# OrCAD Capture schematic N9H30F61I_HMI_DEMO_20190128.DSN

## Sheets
1 Main Block: size B; title: N9H30F51I_HMI_DEMO; rev: 1.0; note: MAIN_BLOCK
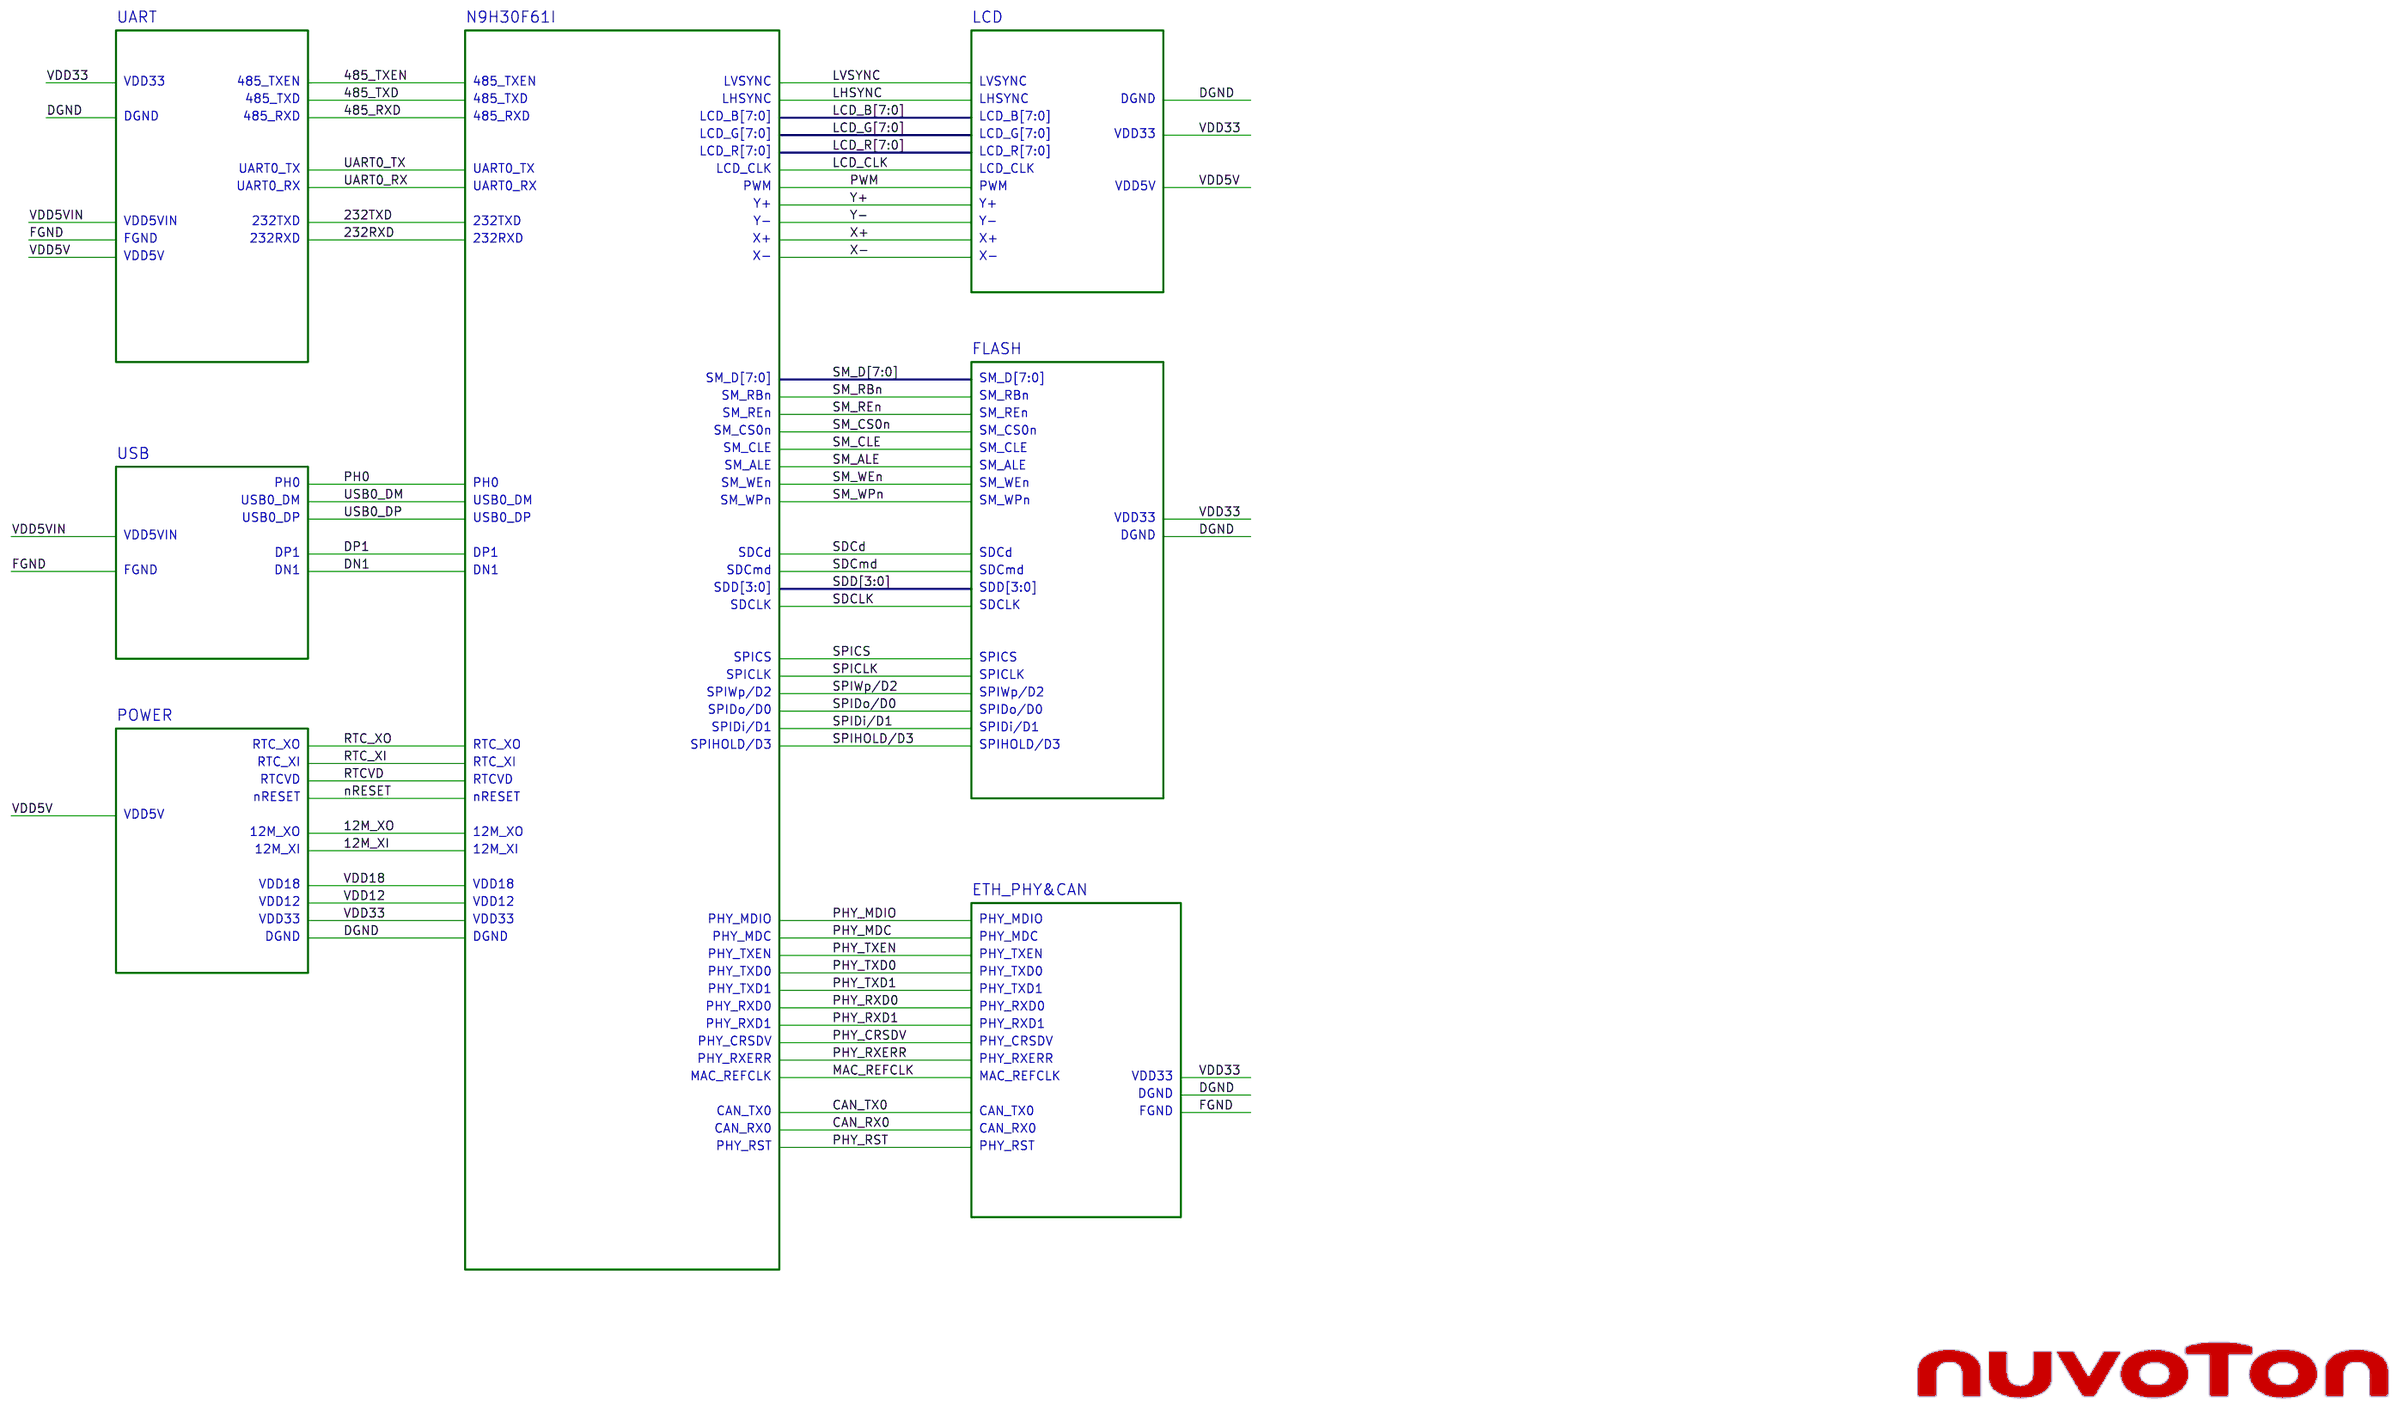
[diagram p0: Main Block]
2 N9H30F61I: size Custom; note: N9H30F51I; block N9H30F61I
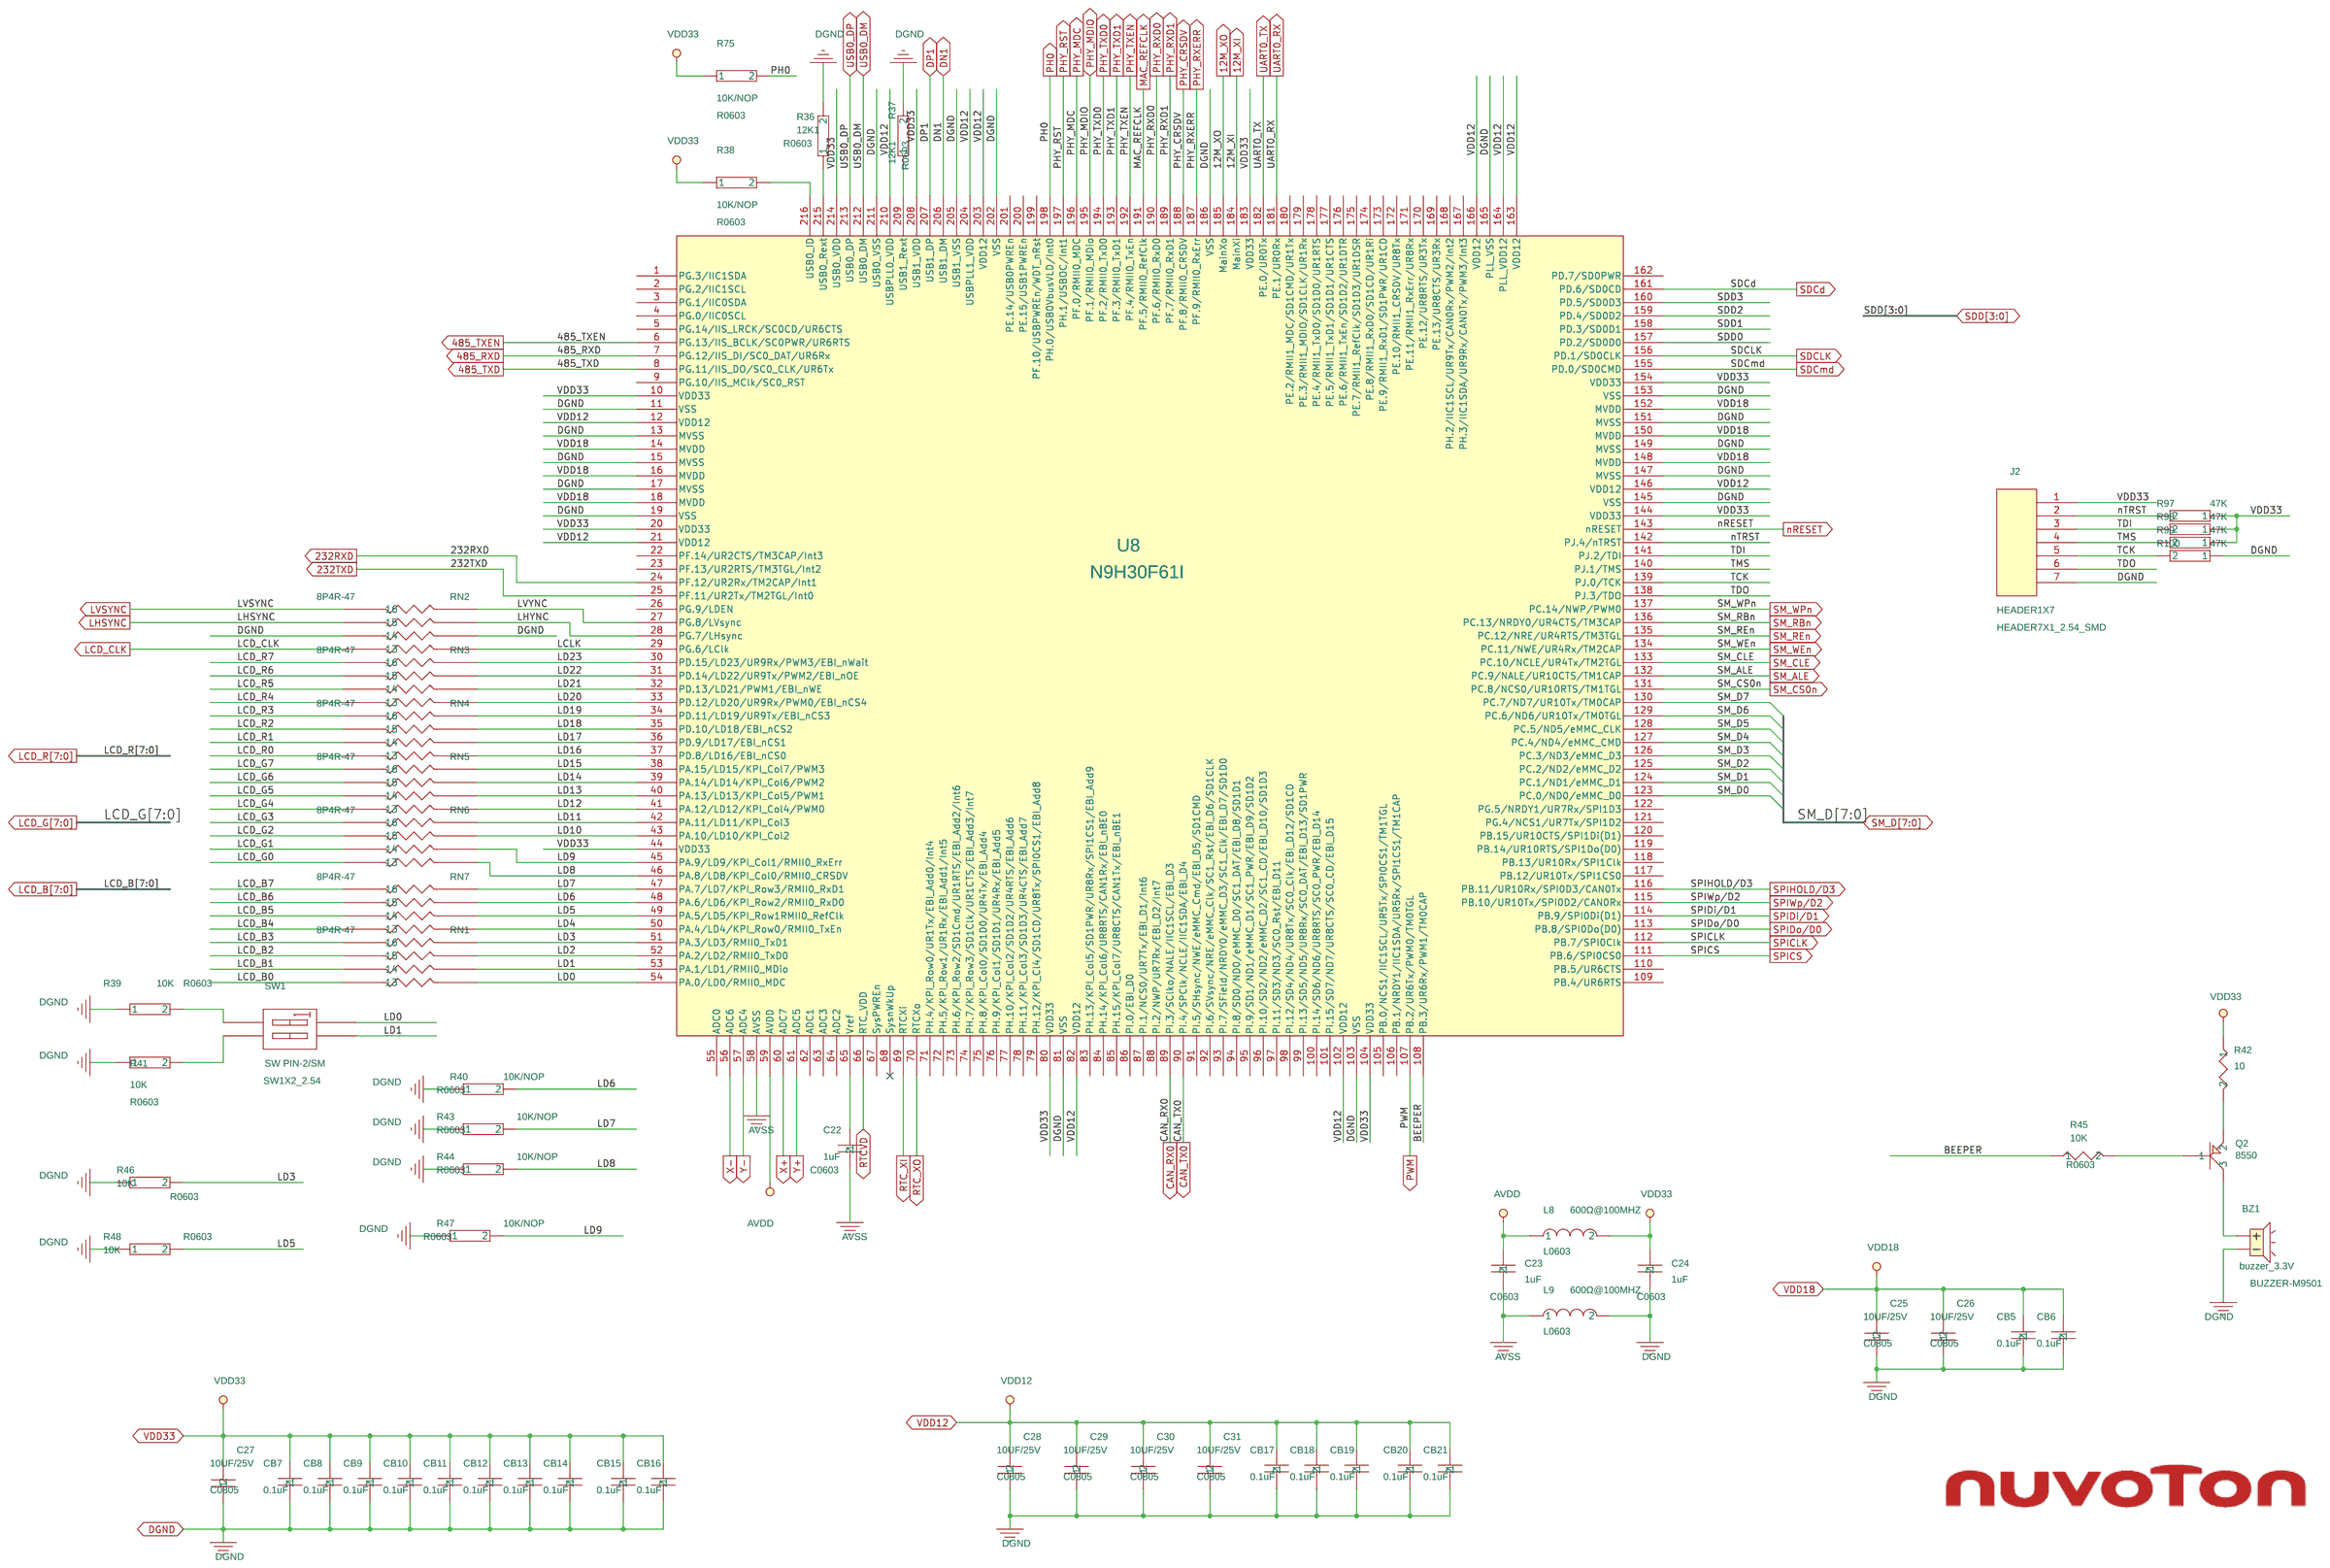
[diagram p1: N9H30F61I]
3 LCD: size B; note: LCD; block LCD
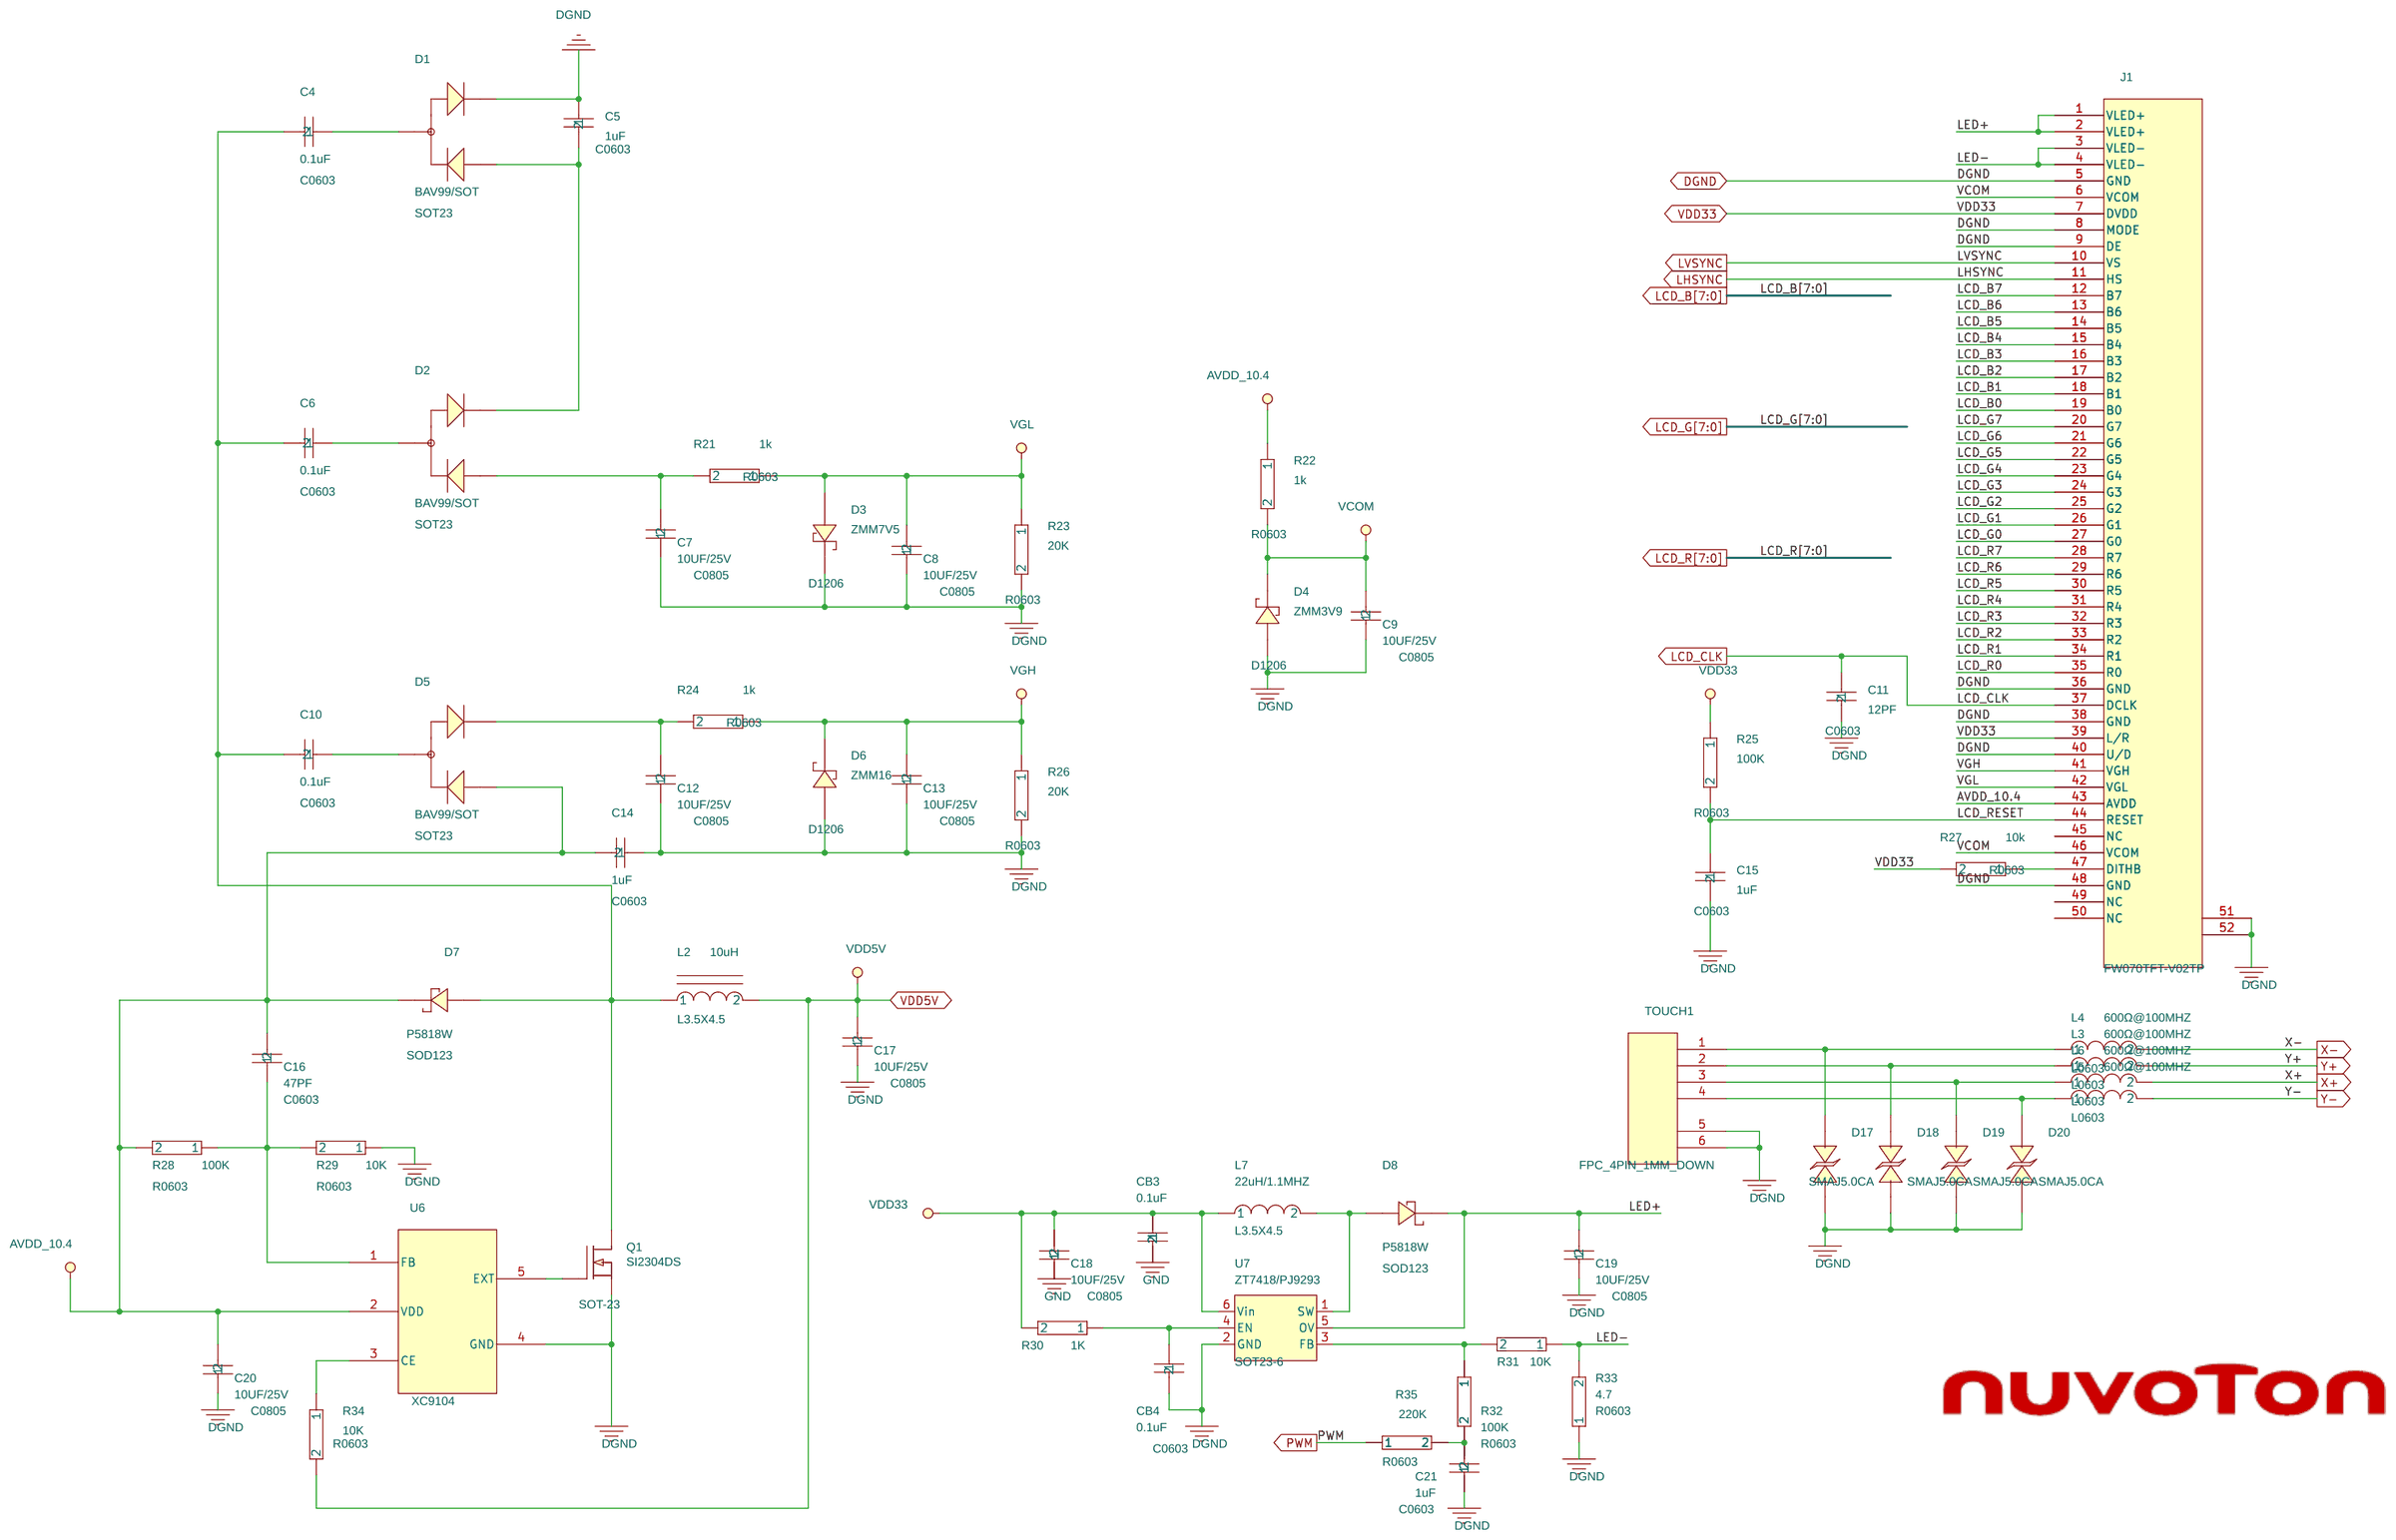
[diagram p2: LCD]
4 Flash: size A; note: Flash; block FLASH
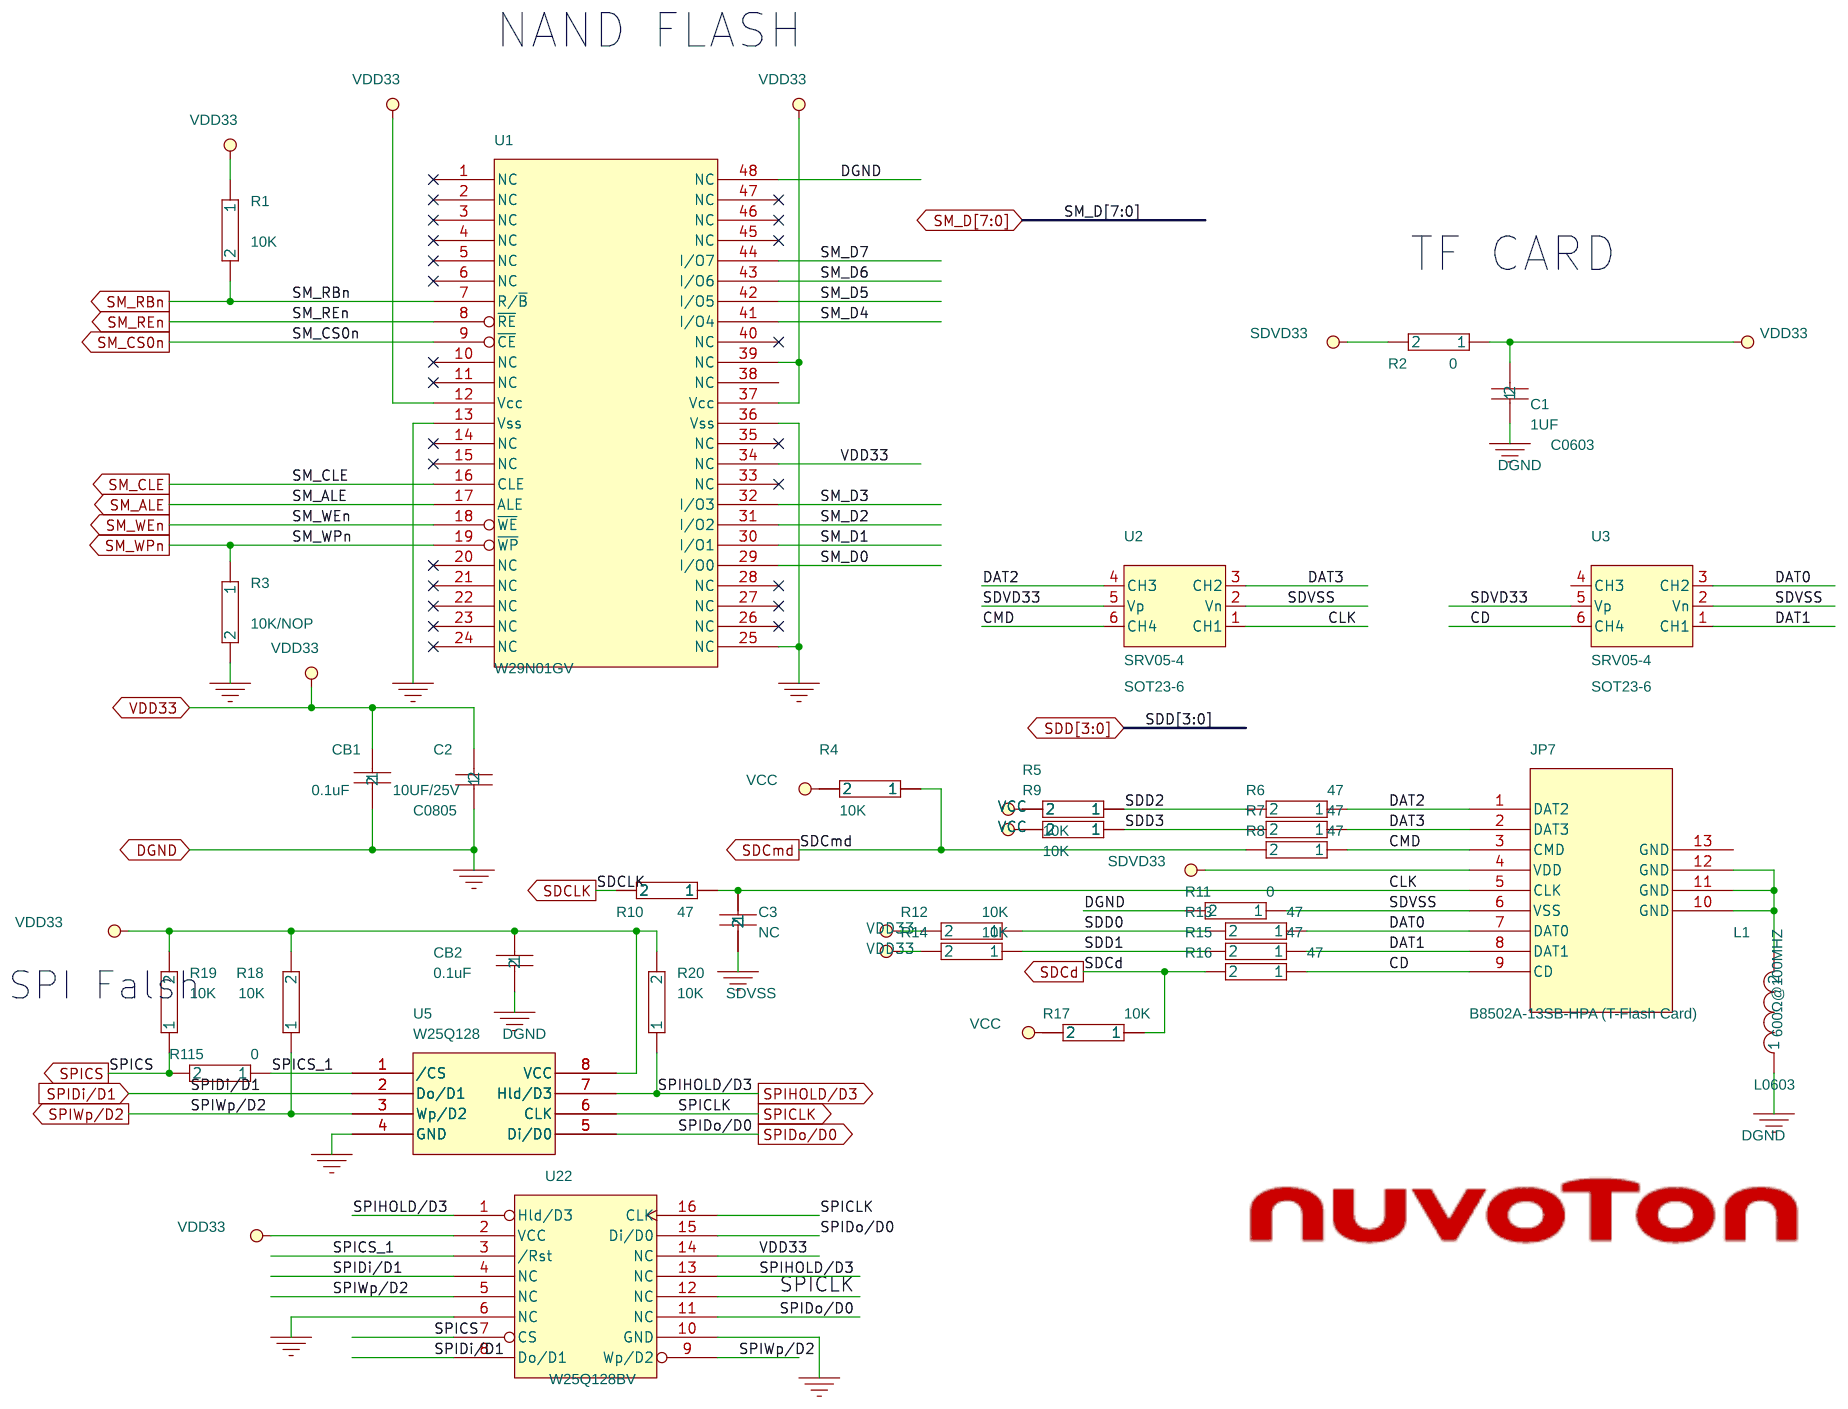
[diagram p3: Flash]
5 ETH_PHY&CAN: size B; note: ETH_PHY&CAN; block ETH_PHY&CAN
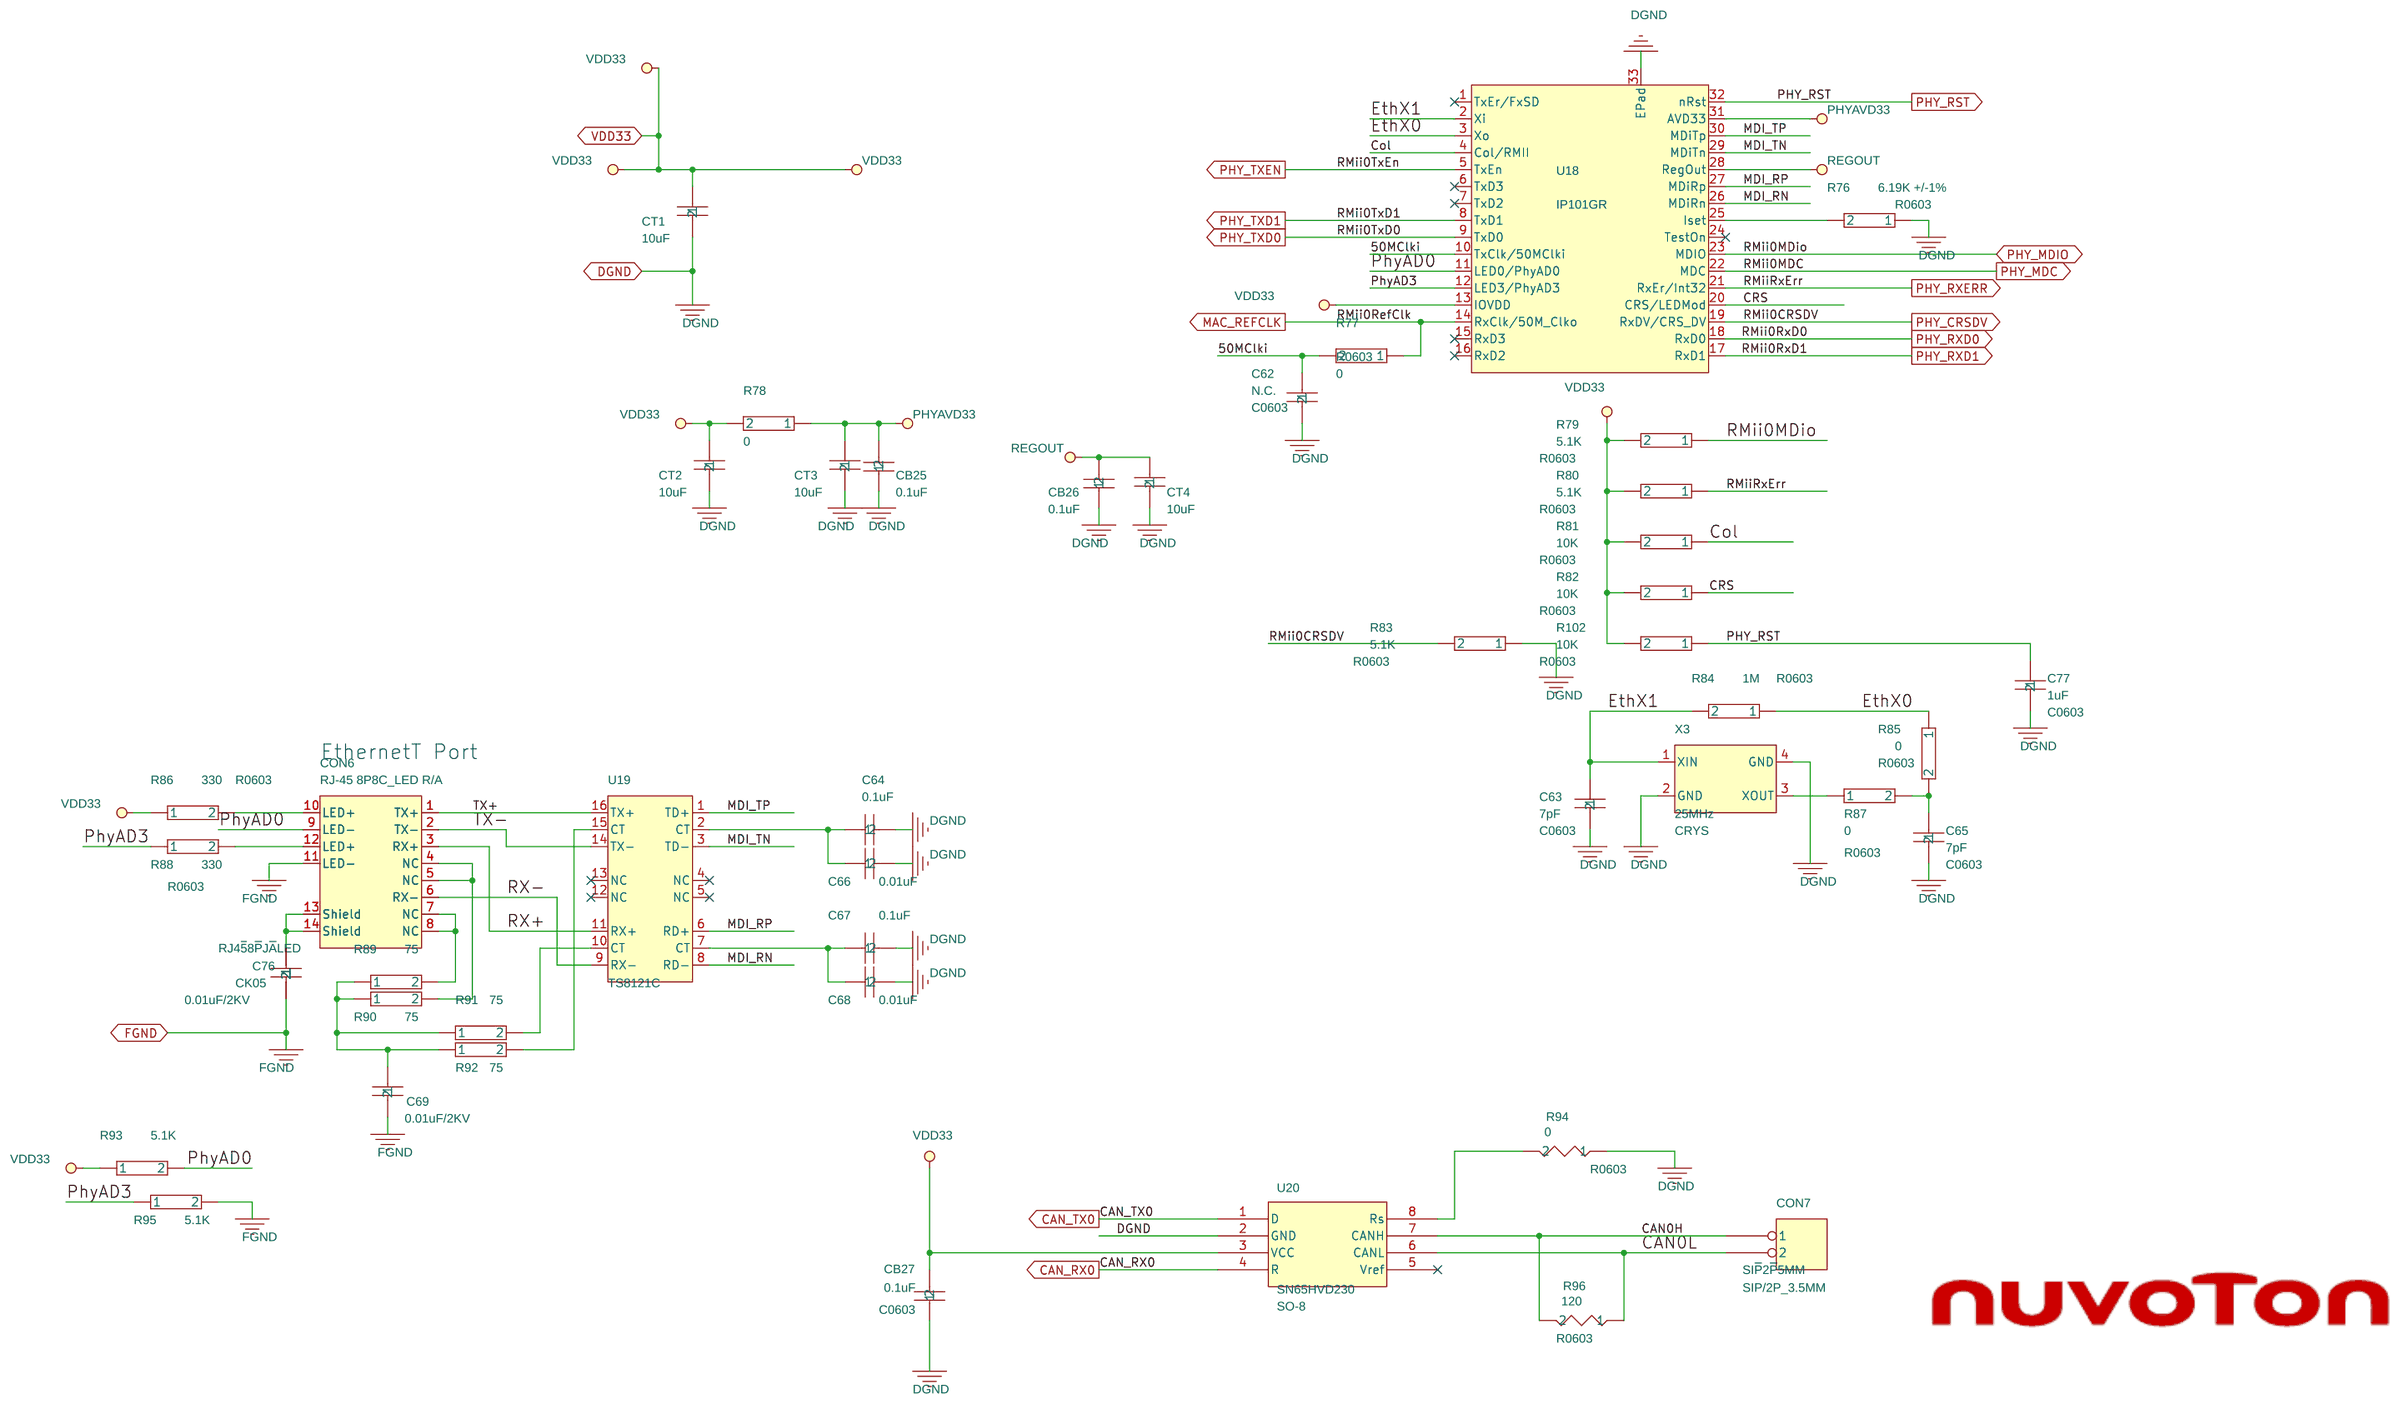
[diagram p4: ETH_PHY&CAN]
6 UART: size B; note: UART; block UART
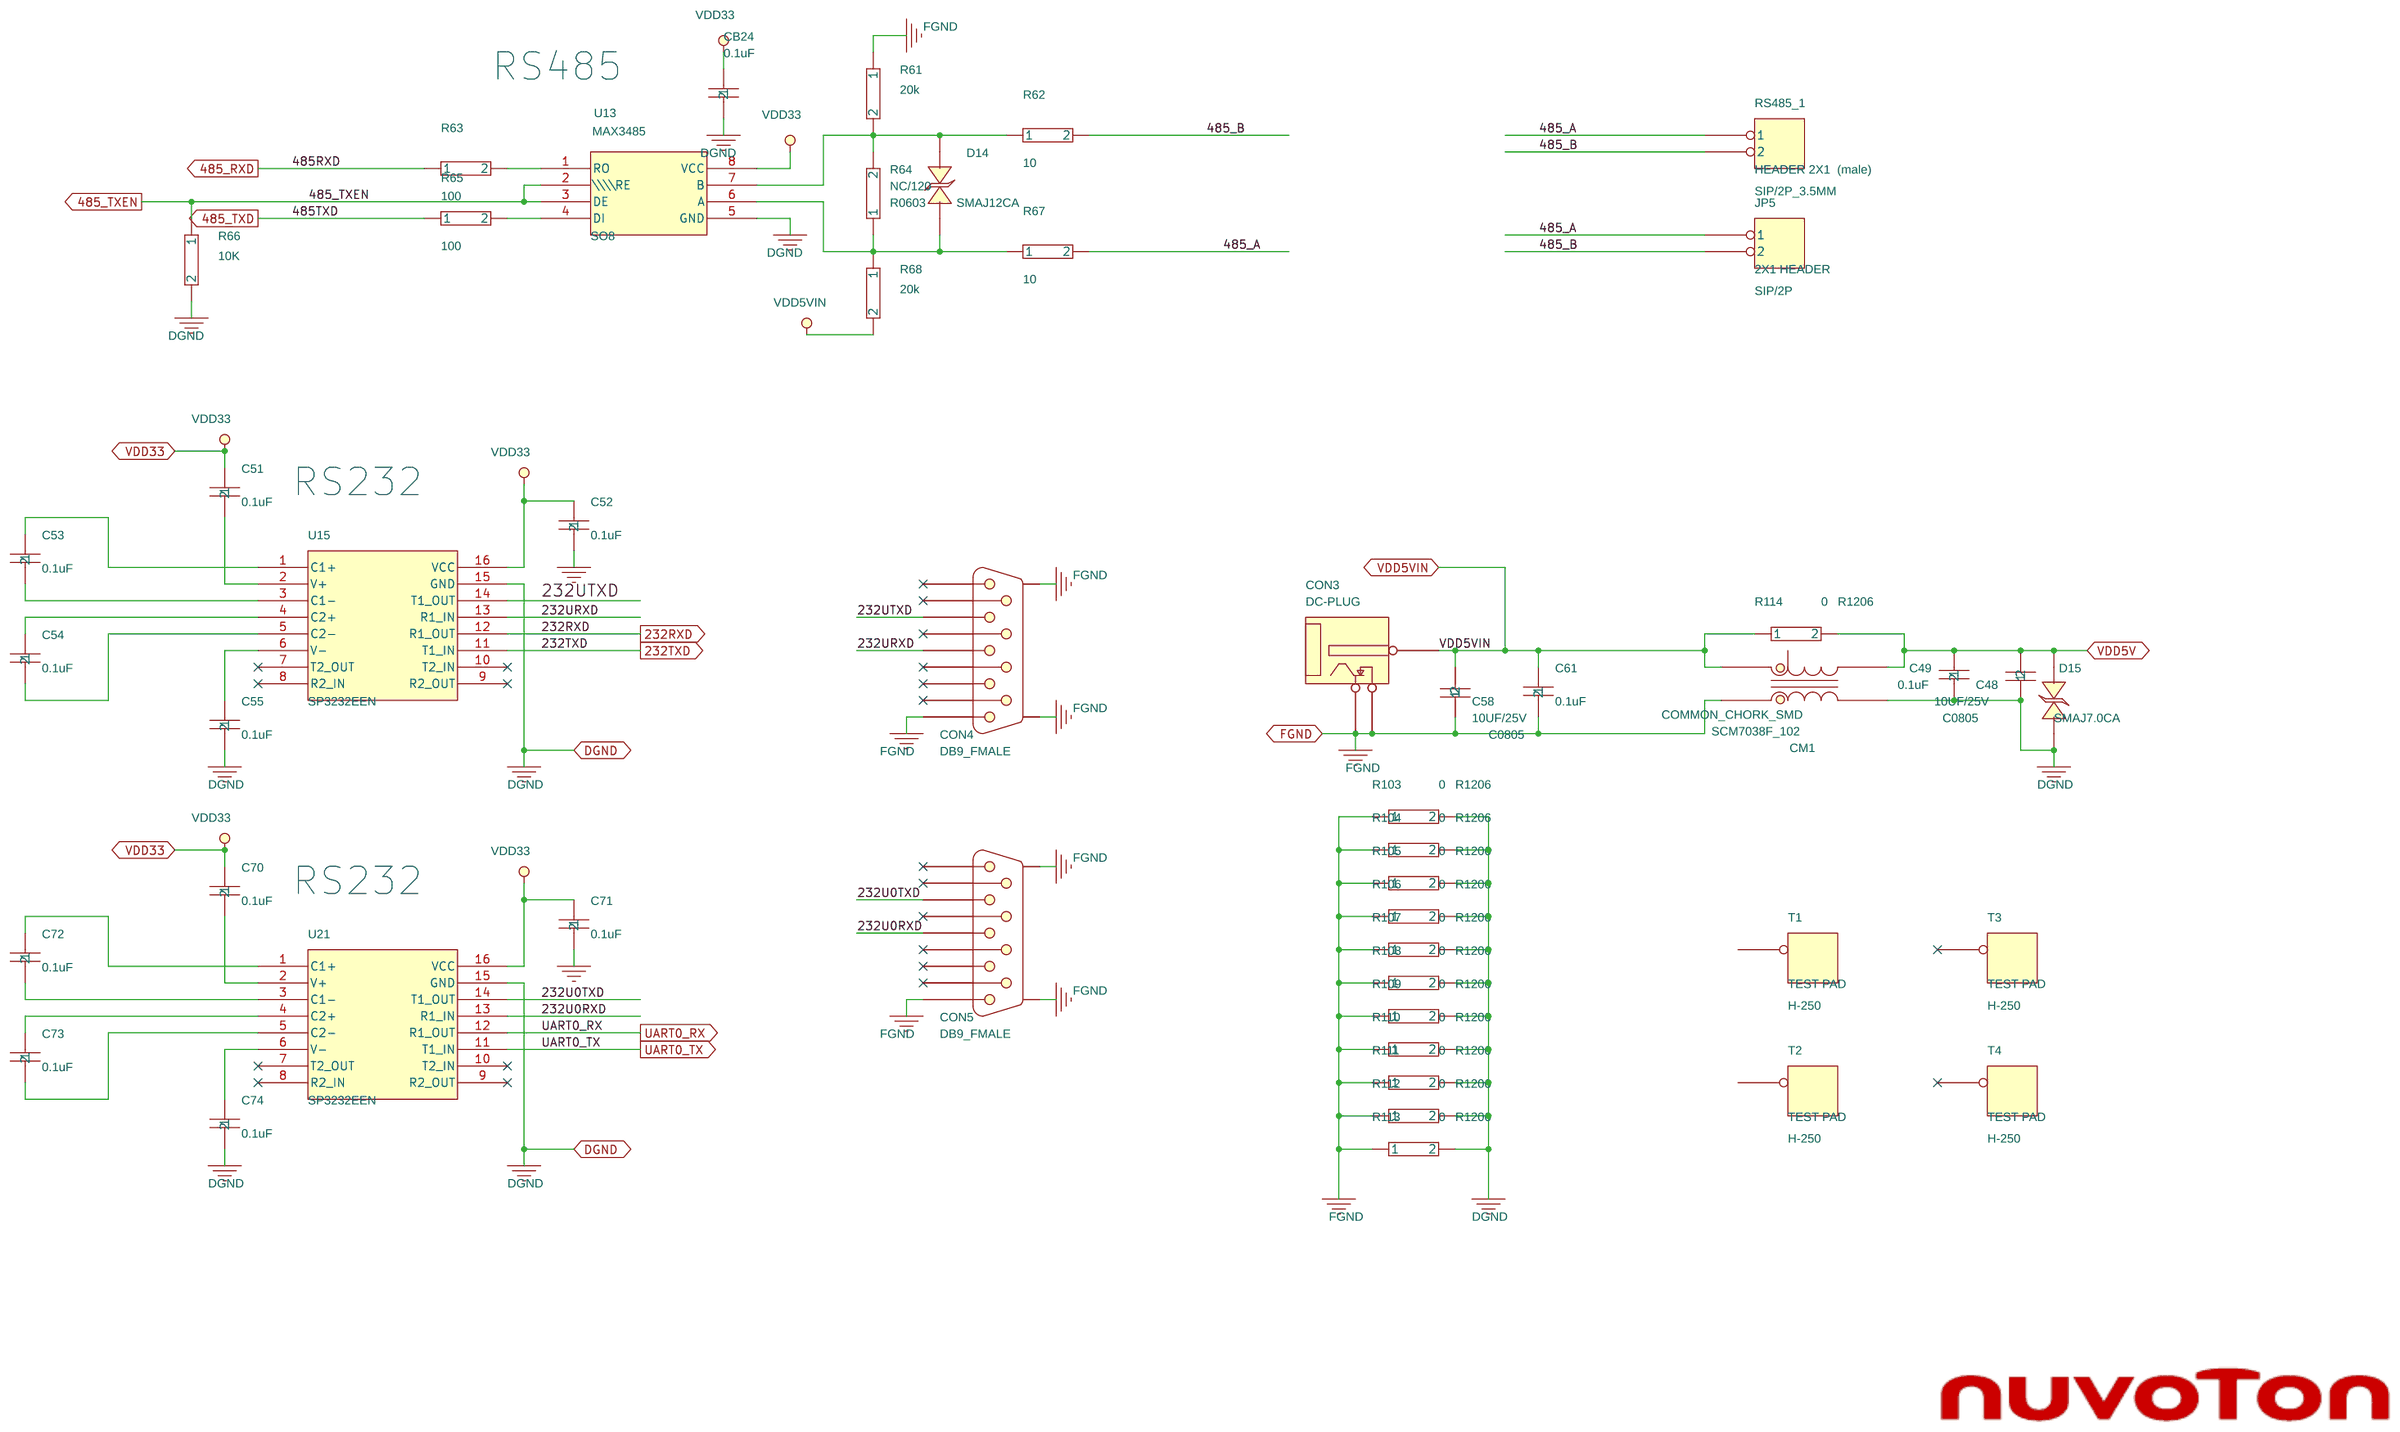
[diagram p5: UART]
7 USB: size A; note: USB; block USB
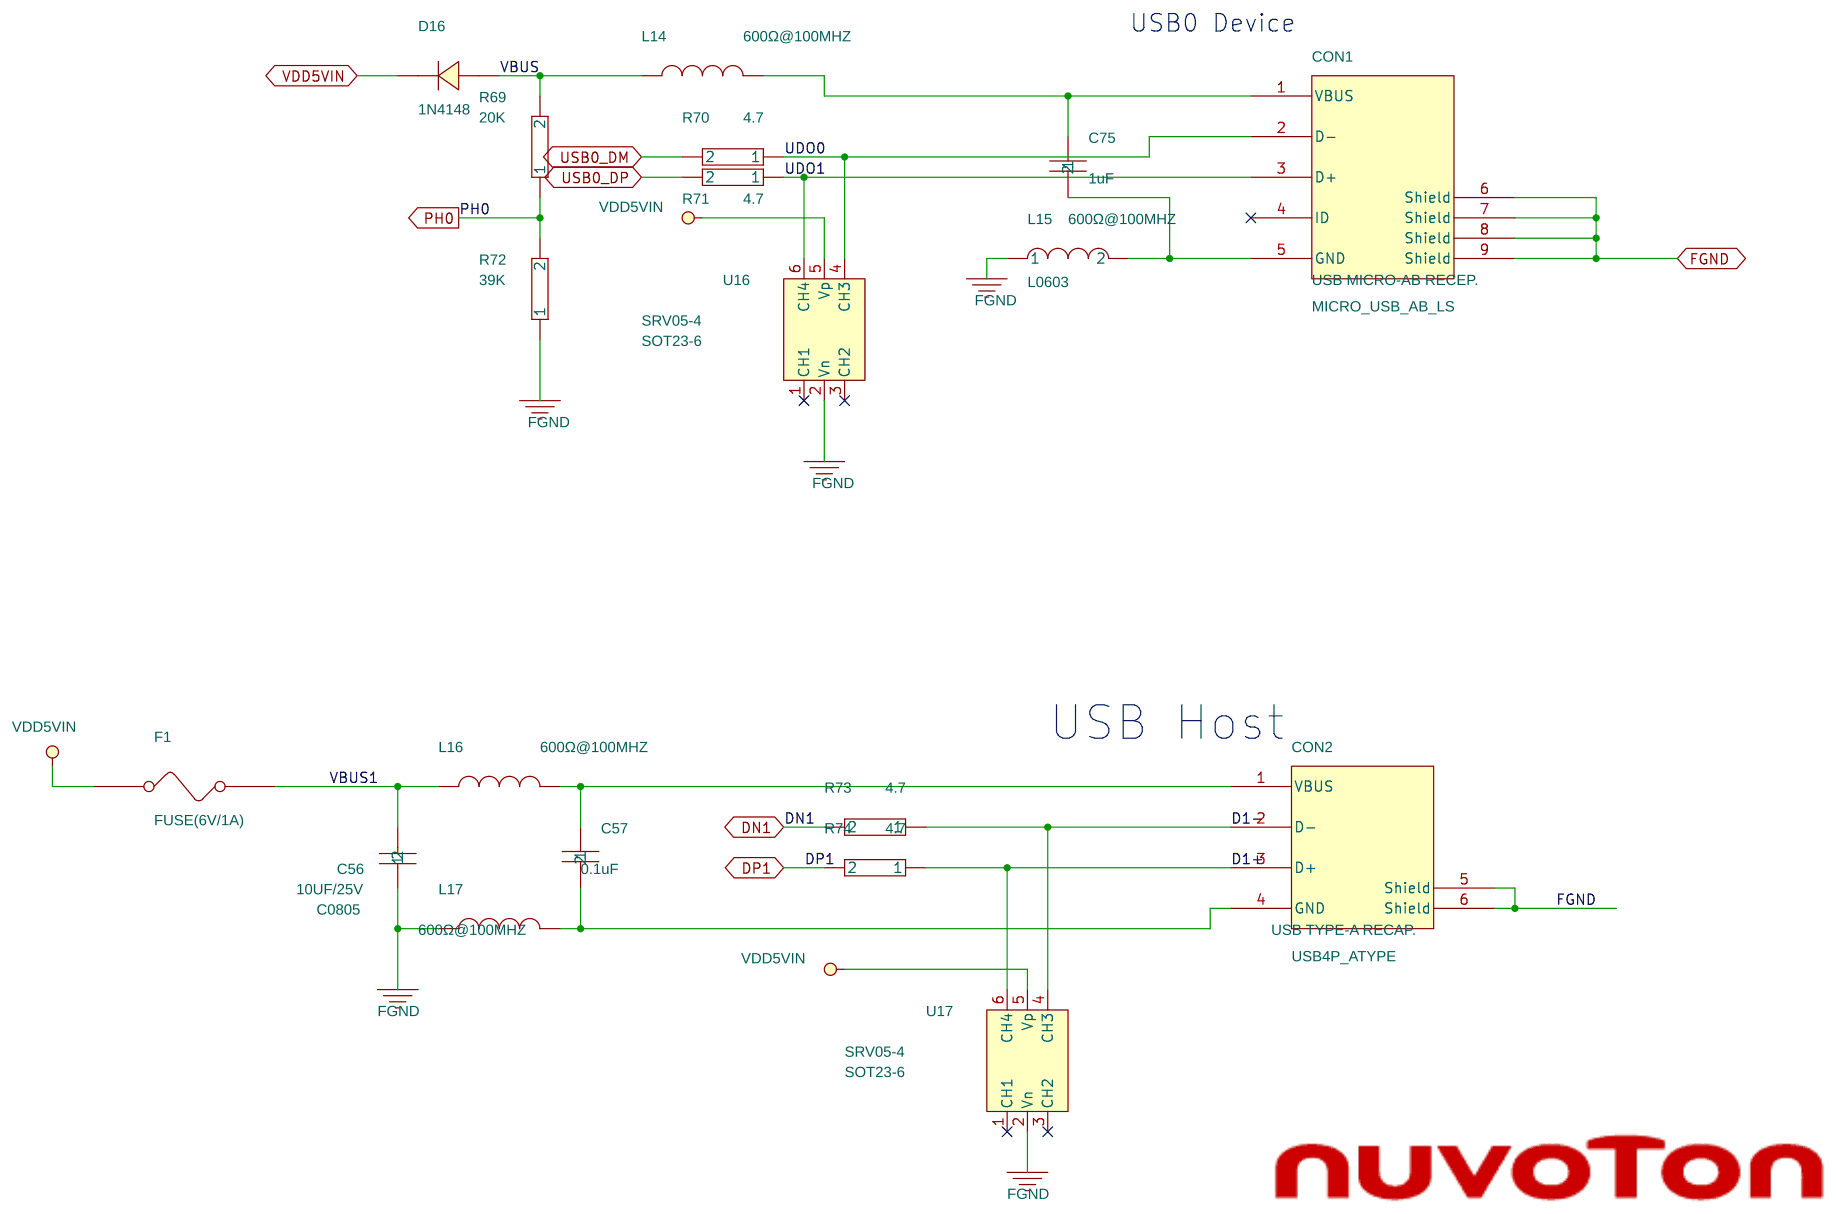
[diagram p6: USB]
8 Power: size A; note: Power; block POWER
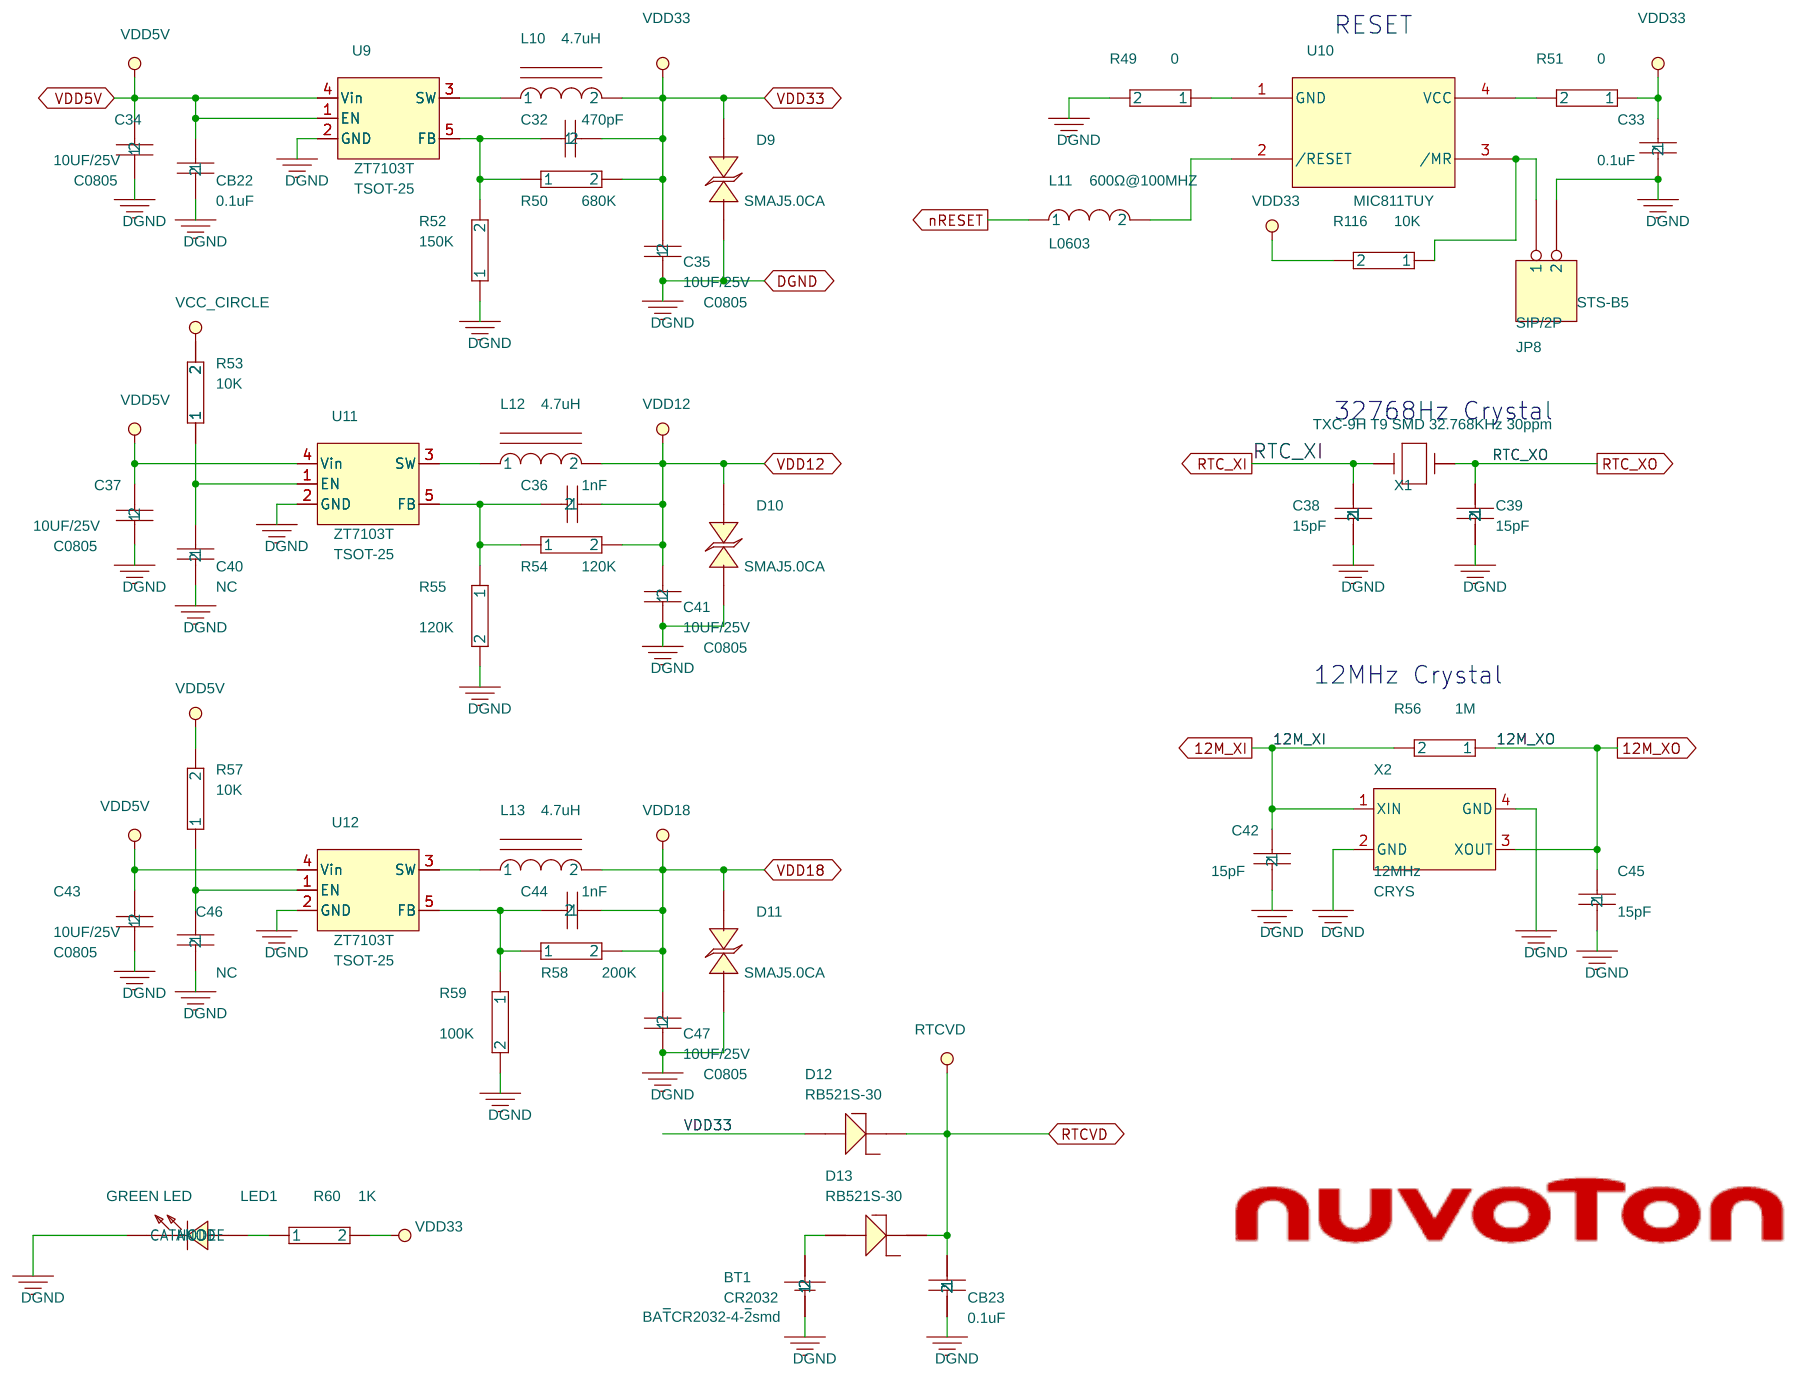
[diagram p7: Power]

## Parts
sheet ETH_PHY&CAN
C62  N.C.  [C0603]
C63  7pF  [C0603]
C64  0.1uF  [C0603]
C65  7pF  [C0603]
C66  0.01uF  [C0603]
C67  0.1uF  [C0603]
C68  0.01uF  [C0603]
C69  0.01uF/2KV  [CK05]
C76  0.01uF/2KV  [CK05]
C77  1uF  [C0603]
CB25  0.1uF  [C0603]
CB26  0.1uF  [C0603]
CB27  0.1uF  [C0603]
CON6  RJ-45 8P8C_LED R/A  [RJ45\8P\JA\LED]
CON7  SIP\2P\5MM  [SIP/2P_3.5MM]
CT1  10uF  [C0805]
CT2  10uF  [C0805]
CT3  10uF  [C0805]
CT4  10uF  [C0805]
R76  6.19K +/-1%  [R0603]
R77  0  [R0603]
R78  0  [R0603]
R79  5.1K  [R0603]
R80  5.1K  [R0603]
R81  10K  [R0603]
R82  10K  [R0603]
R83  5.1K  [R0603]
R84  1M  [R0603]
R85  0  [R0603]
R86  330  [R0603]
R87  0  [R0603]
R88  330  [R0603]
R89  75  [R0603]
R90  75  [R0603]
R91  75  [R0603]
R92  75  [R0603]
R93  5.1K  [R0603]
R94  0  [R0603]
R95  5.1K  [R0603]
R96  120  [R0603]
R102  10K  [R0603]
U18  IP101GR  [QFN32-0.4X4M]
U19  TS8121C  [ST6200T]
U20  SN65HVD230  [SO-8]
X3  25MHz  [CRYS]
sheet Flash
C1  1UF  [C0603]
C2  10UF/25V  [C0805]
C3  NC  [C0603]
CB1  0.1uF  [C0603]
CB2  0.1uF  [C0603]
JP7  B8502A-13SB-HPA (T-Flash Card)  [B8502A-13SB-HPA]
L1  600Ω@100MHZ  [L0603]
R1  10K  [R0603]
R2  0  [R0603]
R3  10K/NOP  [R0603]
R4  10K  [R0603]
R5  10K  [R0603]
R6  47  [R0603]
R7  47  [R0603]
R8  47  [R0603]
R9  10K  [R0603]
R10  47  [R0603]
R11  0  [R0603]
R12  10K  [R0603]
R13  47  [R0603]
R14  10K  [R0603]
R15  47  [R0603]
R16  47  [R0603]
R17  10K  [R0603]
R18  10K  [R0603]
R19  10K  [R0603]
R20  10K  [R0603]
R115  0  [R0603]
U1  W29N01GV  [TQFP48\0.5]
U2  SRV05-4  [SOT23-6]
U3  SRV05-4  [SOT23-6]
U5  W25Q128  [SO8_300_208_150]
U22  W25Q128BV  [SO16_300_208_150]
sheet LCD
C4  0.1uF  [C0603]
C5  1uF  [C0603]
C6  0.1uF  [C0603]
C7  10UF/25V  [C0805]
C8  10UF/25V  [C0805]
C9  10UF/25V  [C0805]
C10  0.1uF  [C0603]
C11  12PF  [C0603]
C12  10UF/25V  [C0805]
C13  10UF/25V  [C0805]
C14  1uF  [C0603]
C15  1uF  [C0603]
C16  47PF  [C0603]
C17  10UF/25V  [C0805]
C18  10UF/25V  [C0805]
C19  10UF/25V  [C0805]
C20  10UF/25V  [C0805]
C21  1uF  [C0603]
CB3  0.1uF  [C0603]
CB4  0.1uF  [C0603]
D1  BAV99/SOT  [SOT23]
D2  BAV99/SOT  [SOT23]
D3  ZMM7V5  [D1206]
D4  ZMM3V9  [D1206]
D5  BAV99/SOT  [SOT23]
D6  ZMM16  [D1206]
D7  P5818W  [SOD123]
D8  P5818W  [SOD123]
D17  SMAJ5.0CA  [SMA]
D18  SMAJ5.0CA  [SMA]
D19  SMAJ5.0CA  [SMA]
D20  SMAJ5.0CA  [SMA]
J1  FW070TFT-V02TP  [FPC_50P_0.5MM]
L2  10uH  [L3.5X4.5]
L3  600Ω@100MHZ  [L0603]
L4  600Ω@100MHZ  [L0603]
L5  600Ω@100MHZ  [L0603]
L6  600Ω@100MHZ  [L0603]
L7  22uH/1.1MHZ  [L3.5X4.5]
Q1  SI2304DS  [SOT-23]
R21  1k  [R0603]
R22  1k  [R0603]
R23  20K  [R0603]
R24  1k  [R0603]
R25  100K  [R0603]
R26  20K  [R0603]
R27  10k  [R0603]
R28  100K  [R0603]
R29  10K  [R0603]
R30  1K  [R0603]
R31  10K  [R0603]
R32  100K  [R0603]
R33  4.7  [R0603]
R34  10K  [R0603]
R35  220K  [R0603]
TOUCH1  FPC_4PIN_1MM_DOWN  [FPC_4PIN_1MM_C]
U6  XC9104  [SOT23-5]
U7  ZT7418/PJ9293  [SOT23-6]
sheet N9H30F61I
BZ1  buzzer_3.3V  [BUZZER-M9501]
C22  1uF  [C0603]
C23  1uF  [C0603]
C24  1uF  [C0603]
C25  10UF/25V  [C0805]
C26  10UF/25V  [C0805]
C27  10UF/25V  [C0805]
C28  10UF/25V  [C0805]
C29  10UF/25V  [C0805]
C30  10UF/25V  [C0805]
C31  10UF/25V  [C0805]
CB5  0.1uF  [C0603]
CB6  0.1uF  [C0603]
CB7  0.1uF  [C0603]
CB8  0.1uF  [C0603]
CB9  0.1uF  [C0603]
CB10  0.1uF  [C0603]
CB11  0.1uF  [C0603]
CB12  0.1uF  [C0603]
CB13  0.1uF  [C0603]
CB14  0.1uF  [C0603]
CB15  0.1uF  [C0603]
CB16  0.1uF  [C0603]
CB17  0.1uF  [C0603]
CB18  0.1uF  [C0603]
CB19  0.1uF  [C0603]
CB20  0.1uF  [C0603]
CB21  0.1uF  [C0603]
J2  HEADER1X7  [HEADER7X1_2.54_SMD]
L8  600Ω@100MHZ  [L0603]
L9  600Ω@100MHZ  [L0603]
Q2  8550  [SOT23]
R36  12K1  [R0603]
R37  12K1  [R0603]
R38  10K/NOP  [R0603]
R39  10K  [R0603]
R40  10K/NOP  [R0603]
R41  10K  [R0603]
R42  10  [R0603]
R43  10K/NOP  [R0603]
R44  10K/NOP  [R0603]
R45  10K  [R0603]
R46  10K  [R0603]
R47  10K/NOP  [R0603]
R48  10K  [R0603]
R75  10K/NOP  [R0603]
R97  47K  [R0603]
R98  47K  [R0603]
R99  47K  [R0603]
R100  47K  [R0603]
RN1  8P4R-47  [SMTRP8]
RN2  8P4R-47  [SMTRP8]
RN3  8P4R-47  [SMTRP8]
RN4  8P4R-47  [SMTRP8]
RN5  8P4R-47  [SMTRP8]
RN6  8P4R-47  [SMTRP8]
RN7  8P4R-47  [SMTRP8]
SW1  SW PIN-2/SM  [SW1X2_2.54]
U8  N9H30F61I  [LQFP-216]
sheet Power
BT1  CR2032  [BAT\CR2032-4-2\smd]
C32  470pF  [C0603]
C33  0.1uF  [C0603]
C34  10UF/25V  [C0805]
C35  10UF/25V  [C0805]
C36  1nF  [C0603]
C37  10UF/25V  [C0805]
C38  15pF  [C0603]
C39  15pF  [C0603]
C40  NC  [C0603]
C41  10UF/25V  [C0805]
C42  15pF  [C0603]
C43  10UF/25V  [C0805]
C44  1nF  [C0603]
C45  15pF  [C0603]
C46  NC  [C0603]
C47  10UF/25V  [C0805]
CB22  0.1uF  [C0603]
CB23  0.1uF  [C0603]
D9  SMAJ5.0CA  [SMA]
D10  SMAJ5.0CA  [SMA]
D11  SMAJ5.0CA  [SMA]
D12  RB521S-30  [SOD-523]
D13  RB521S-30  [SOD-523]
JP8  SIP/2P  [STS-B5]
L10  4.7uH  [L3.5X4.5]
L11  600Ω@100MHZ  [L0603]
L12  4.7uH  [L3.5X4.5]
L13  4.7uH  [L3.5X4.5]
LED1  GREEN LED  [LED0603]
R49  0  [R0603]
R50  680K  [R0603]
R51  0  [R0603]
R52  150K  [R0603]
R53  10K  [R0603]
R54  120K  [R0603]
R55  120K  [R0603]
R56  1M  [R0603]
R57  10K  [R0603]
R58  200K  [R0603]
R59  100K  [R0603]
R60  1K  [R0603]
R116  10K  [R0603]
U9  ZT7103T  [TSOT-25]
U10  MIC811TUY  [SOT143]
U11  ZT7103T  [TSOT-25]
U12  ZT7103T  [TSOT-25]
X1  TXC-9H T9 SMD 32.768KHz 30ppm  [XTAL_2P/1.5mm]
X2  12MHz  [CRYS]
sheet UART
C48  10UF/25V  [C0805]
C49  0.1uF  [C0603]
C51  0.1uF  [C0603]
C52  0.1uF  [C0603]
C53  0.1uF  [C0603]
C54  0.1uF  [C0603]
C55  0.1uF  [C0603]
C58  10UF/25V  [C0805]
C61  0.1uF  [C0603]
C70  0.1uF  [C0603]
C71  0.1uF  [C0603]
C72  0.1uF  [C0603]
C73  0.1uF  [C0603]
C74  0.1uF  [C0603]
CB24  0.1uF  [C0603]
CM1  SCM7038F_102  [COMMON_CHORK_SMD]
CON3  DC-PLUG  [POWRJACK\3P]
CON4  DB9_FMALE  [DB9_FMALE]
CON5  DB9_FMALE  [DB9_FMALE]
D14  SMAJ12CA  [SMA]
D15  SMAJ7.0CA  [SMA]
JP5  2X1 HEADER  [SIP/2P]
R61  20k  [R0603]
R62  10  [R0603]
R63  100  [R0603]
R64  NC/120  [R0603]
R65  100  [R0603]
R66  10K  [R0603]
R67  10  [R0603]
R68  20k  [R0603]
R103  0  [R1206]
R104  0  [R1206]
R105  0  [R1206]
R106  0  [R1206]
R107  0  [R1206]
R108  0  [R1206]
R109  0  [R1206]
R110  0  [R1206]
R111  0  [R1206]
R112  0  [R1206]
R113  0  [R1206]
R114  0  [R1206]
RS485_1  HEADER 2X1  (male)  [SIP/2P_3.5MM]
T1  TEST PAD  [H-250]
T2  TEST PAD  [H-250]
T3  TEST PAD  [H-250]
T4  TEST PAD  [H-250]
U13  MAX3485  [SO8]
U15  SP3232EEN  [SOP16/150]
U21  SP3232EEN  [SOP16/150]
sheet USB
C56  10UF/25V  [C0805]
C57  0.1uF  [C0603]
C75  1uF  [C0603]
CON1  USB MICRO-AB RECEP.  [MICRO_USB_AB_LS]
CON2  USB TYPE-A RECAP.  [USB4P_ATYPE]
D16  1N4148  [1N4148]
F1  FUSE(6V/1A)  [FUSE_SMD]
L14  600Ω@100MHZ  [L0603]
L15  600Ω@100MHZ  [L0603]
L16  600Ω@100MHZ  [L0603]
L17  600Ω@100MHZ  [L0603]
R69  20K  [R0603]
R70  4.7  [R0603]
R71  4.7  [R0603]
R72  39K  [R0603]
R73  4.7  [R0603]
R74  4.7  [R0603]
U16  SRV05-4  [SOT23-6]
U17  SRV05-4  [SOT23-6]

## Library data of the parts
C18 C22 C34 C62 = CAP_NP_14
C11 C32 C63 CB6 = CAP_NP_5
C8 C31 C45 C64 = CAP_NP_12
C10 C28 C39 C65 = CAP_NP_6
C16 C44 C66 CB17 = CAP_NP_11
C20 C43 C67 CB21 = CAP_NP_4
C9 C68 CB12 CB22 = CAP_NP_13
C2 C14 C46 C49 C69 CB5 = CAP_NP_2
C7 C24 C36 C56 C58 C76 CB2 = CAP_NP
C15 C37 C77 CB15 = CAP_NP_9
C5 C41 CB11 CB25 = CAP_NP_8
C3 C6 C40 CB20 CB24 CB26 = CAP_NP_1
CB27 = CAP-C: Package: 0603
CON6 = RJ45_SHLD_0
CON7 JP8 RS485_1 = HEADER_2
C13 C25 C42 CT1 = CAP_NP_10
C21 C38 CB8 CT2 = CAP_NP_7
C1 C17 C47 C48 CB7 CT3 = CAP_NP_3
C4 C23 C35 CT4 = CAP_NP_15
R11 R23 R54 R76 R99 R106 = R_11
R9 R68 R77 R100 = R_15
R16 R65 R78 = R_18
R3 R21 R48 R59 R72 R79 R110 = R_1
R7 R29 R43 R80 R103 = R_13
R18 R47 R52 R81 R104 = R_10
R17 R25 R44 R49 R63 R82 = R_12
R1 R37 R51 R71 R83 R109 = R_4
R14 R27 R57 R67 R84 R97 = R_6
R5 R22 R40 R53 R69 R85 R108 = R
R10 R34 R36 R60 R86 R112 = R_7
R32 R41 R58 R73 R87 R111 R115 = R_5
R2 R24 R38 R55 R61 R74 R88 = R_2
R4 R28 R39 R89 R107 = R_14
R20 R62 R90 = R_16
R15 R35 R56 R91 R98 = R_9
R12 R33 R46 R50 R70 R92 R114 = R_3
R8 R66 R93 = R_17
R45 R94 = R_0_1: Package: 0603
R6 R26 R75 R95 R105 R116 = R_8
R42 R96 = R_0: Package: 0603
R13 R102 R113 = R_19
U18 = IP101GA_0
U19 = PE-68515_1
U20 = SN65HVD230
X3 = Crystal_SMD_2: Vendor: Aurum
C33 C57 C72 CB1 = CAP-B
JP7 = B8502A-13SB-HPA_(T-Flash_Card)
L1 L3 L8 L11 L15 = INDUCTOR
R19 = R_20
U1 = K9F5608U0D
U2 U3 U16 U17 = PJ9293_0
U5 = W55X10_2
U22 = W25Q128BV_4
C12 C29 = CAP_NP_17
C19 CB16 CB23 = CAP_NP_16
CB3 = CAP-B: Package: C0402
CB4 = CAP-B_1: Package: C0402
D1 D2 D5 = BAV99_SOT
D3 D4 D6-D8 = ZHCS750_SOT_1
D9-D11 D14 D15 D17-D20 = DIODE_TAZ_BI-DIR
J1 = AT070TN94_0
L2 L10 = INDUCTOR_IRON
L4 = INDUCTOR_2
L5 L9 = INDUCTOR_1
L6 = INDUCTOR_4
L7 = INDUCTOR_3: Package: L-3
Q1 = MOSFET_N_0
R30 = R_4: Package: R0402
R31 = R_10: Package: R0402
TOUCH1 = HEADER1X7_0
U6 = XC9104
U7 = PJ9293
BZ1 = BUZZER: HUA-JIE/PAC-WT-1205-7; Class: DISCRETE; Colay_Alternate: N/A; Colay_Group: N/A; Critical_Part: N; Data_Sheet: K:\DataSheet\09-INDUCTOR\09G050000400.pdf; Manufacture: HUAJIE; Modify_Data: 2005/5/9; Optional: N/A; Package_Type: DIP; Part Number: 09G050000400; Part Type: 09INDUCTOR\BUZZER; Subsystem_ID: N/A; metal_fabrication: 00000011
C26 = CAP_NP_18
C27 = CAP_NP_22
C30 = CAP_NP_26
CB9 = CAP_NP_20
CB10 = CAP_NP_24
CB13 = CAP_NP_21
CB14 = CAP_NP_25
CB18 = CAP_NP_19
CB19 = CAP_NP_23
J2 = HEADER1X7_2
Q2 = PNP_1
RN1-RN7 = 4R_0
SW1 = SW_DIP-2_SM
U8 = NUC970_1
BT1 = BATTERY_ELEM
D12 D13 = ZENAR_0: Package: D
L12 = INDUCTOR_IRON_2
L13 = INDUCTOR_IRON_1
LED1 = LED_DIP
U9 U11 U12 = ZT7103S_0
U10 = MIC811TUY
X1 = MA306_SM_2: Vendor: TXC
X2 = Crystal_SMD_2
C51 = CAP-B_2
C52 = CAP-B_3
C53 = CAP-B_8
C54 C75 = CAP-B_1
C55 = CAP-B_5
C61 = CAP-B_4
C70 = CAP-B_6
C71 = CAP-B_10
C73 = CAP-B_7
C74 = CAP-B_9
CM1 = CHOKE_CM_0: 60uH Rdc=40Ω 800@80MHz Dip; Part Number: 20-020002-92; PoE: Poe
CON3 = Power_Jack
CON4 CON5 = CONNECTOR_DB9_0
JP5 T1-T4 = HEADER_2_1
R64 = R_9: Package: 0603
U13 = ADM232_1_v2: Package: DIP16\SO
U15 U21 = ADM232_0
CON1 = USB_type_B_mini_connector
CON2 = USB_type_A_connector
D16 = DIODE
F1 = FUSE
L14 L16 L17 = INDUCTOR_0

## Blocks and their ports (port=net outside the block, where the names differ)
UART = schematic UART, on sheet Main Block: 485_RXD, 485_TXD, 485_TXEN, VDD33, 232RXD, 232TXD, DGND, UART0_RX, UART0_TX, FGND, VDD5V, VDD5VIN
N9H30F61I = schematic N9H30F61I, on sheet Main Block: 485_TXEN, 485_TXD, 485_RXD, UART0_TX, UART0_RX, 232TXD, 232RXD, PH0, USB0_DM, USB0_DP, DP1, DN1, RTC_XO, RTC_XI, nRESET, 12M_XO, 12M_XI, VDD18, VDD12, VDD33, DGND, LVSYNC, LHSYNC, LCD_B[7:0], LCD_G[7:0], LCD_R[7:0], LCD_CLK, SM_D[7:0], SM_RBn, SM_REn, SM_CS0n, SM_CLE, SM_ALE, SM_WEn, SM_WPn, SPICS, SPICLK, SPIWp/D2, SPIDo/D0, SPIDi/D1, SPIHOLD/D3, RTCVD, Y+, Y-, X+, X-, PWM, SDCd, SDCmd, SDD[3:0], SDCLK, PHY_MDIO, PHY_MDC, PHY_TXEN, PHY_TXD0, PHY_TXD1, PHY_RXD0, PHY_RXD1, PHY_CRSDV, PHY_RXERR, MAC_REFCLK, CAN_TX0, CAN_RX0, PHY_RST
LCD = schematic LCD, on sheet Main Block: DGND, VDD33, LVSYNC, LHSYNC, LCD_B[7:0], LCD_G[7:0], LCD_R[7:0], LCD_CLK, Y+, X-, Y-, X+, PWM, VDD5V
POWER = schematic Power, on sheet Main Block: VDD5V, VDD33, VDD12, VDD18, RTC_XO, RTC_XI, 12M_XI, 12M_XO, nRESET, DGND, RTCVD
FLASH = schematic Flash, on sheet Main Block: SM_D[7:0], SM_RBn, SM_REn, SM_CS0n, SM_CLE, SM_ALE, SM_WEn, SM_WPn, VDD33, DGND, SPICS, SPICLK, SPIWp/D2, SPIDo/D0, SPIDi/D1, SPIHOLD/D3, SDD[3:0], SDCmd, SDCd, SDCLK
USB = schematic USB, on sheet Main Block: USB0_DM, USB0_DP, PH0, VDD5VIN, FGND, DN1, DP1
ETH_PHY&CAN = schematic ETH_PHY&CAN, on sheet Main Block: PHY_RXD0, PHY_RXD1, PHY_CRSDV, PHY_MDIO, PHY_MDC, PHY_RXERR, MAC_REFCLK, PHY_TXEN, PHY_TXD0, PHY_TXD1, VDD33, DGND, CAN_TX0, CAN_RX0, FGND, PHY_RST

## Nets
AVDD: C23.1 L8.1 U8.59(AVDD)
AVDD_10.4: C14.2 C16.2 C20.2 D5.1 D7.2(CATHODE) J1.43(AVDD) R22.1 R28.2 U6.2(VDD)
AVSS: C22.2 C23.2 L9.1 U8.58(AVSS)
DGND: BT1.1 BZ1.2(-) C1.1 C2.1 C5.1 C7.1 C8.1 C9.1 C11.2 C12.1 C13.1 C14.1 C15.2 C17.1 C18.1 C19.1 C20.1 C21.1 C24.2 C25.1 C26.1 C27.1 C28.1 C29.1 C30.1 C31.1 C33.2 C34.1 C35.1 C37.1 C38.2 C39.2 C40.2 C41.1 C42.2 C43.1 C45.2 C46.2 C47.1 C48.1 C49.2 C52.2 C55.2 C62.2 C63.2 C64.2 C65.2 C66.2 C67.2 C68.2 C71.2 C74.2 C77.2 CB1.2 CB2.2 CB3.2 CB4.2 CB5.2 CB6.2 CB7.2 CB8.2 CB9.2 CB10.2 CB11.2 CB12.2 CB13.2 CB14.2 CB15.2 CB16.2 CB17.2 CB18.2 CB19.2 CB20.2 CB21.2 CB22.2 CB23.2 CB24.2 CB25.1 CB26.1 CB27.1 CM1.3 CT1.2 CT2.2 CT3.2 CT4.2 D1.2 D3.2(CATHODE) D4.1(ANODE) D6.1(ANODE) D9.1 D10.1 D11.1 D15.1 D17.1 D18.1 D19.1 D20.1 J1.5(GND) J1.8(MODE) J1.9(DE) J1.36(GND) J1.38(GND) J1.40(U/D) J1.48(GND) J1.51 J1.52 J2.7 JP8.2 L1.1 L9.2 LED1.2(CATHODE) Q1.2(SOURCE) R3.2 R11.2 R23.2 R26.2 R29.1 R33.1 R36.2 R37.2 R39.1 R40.1 R41.1 R43.1 R44.1 R46.1 R47.1 R48.1 R49.2 R52.1 R55.2 R59.2 R66.2 R76.1 R83.1 R94.1 R100.1 R103.2 R104.2 R105.2 R106.2 R107.2 R108.2 R109.2 R110.2 R111.2 R112.2 R113.2 RN2.3 RN2.6(14) TOUCH1.5 TOUCH1.6 U1.13(Vss) U1.25(NC) U1.36(Vss) U1.48(NC) U5.4(GND) U6.4(GND) U7.2(GND) U8.11(VSS) U8.13(MVSS) U8.15(MVSS) U8.17(MVSS) U8.19(VSS) U8.81(VSS) U8.103(VSS) U8.145(VSS) U8.147(MVSS) U8.149(MVSS) U8.151(MVSS) U8.153(VSS) U8.165(PLL_VSS) U8.186(VSS) U8.202(VSS) U8.205(USB1_VSS) U8.211(USB0_VSS) U9.2(GND) U11.2(GND) U12.2(GND) U13.5(GND) U15.15(GND) U18.33(EPad) U20.2(GND) U21.15(GND) U22.6(NC) U22.10(GND) X2.2(GND) X2.4(GND) X3.2(GND) X3.4(GND)
USB/VBUS: D16.1(ANODE) L14.1 R69.2
USB/VBUS1: C56.2 F1.1 L16.1
VDD5V: C17.2 C34.2 C37.2 C43.2 C48.2 C49.1 CB22.1 CM1.2 D15.2 L2.2 R34.2 R53.2 R57.2 R114.2 U9.1(EN) U9.4(Vin) U11.4(Vin) U12.4(Vin)
VDD5VIN: C58.2 C61.1 CM1.1 CON3.1 D16.2(CATHODE) F1.2 R68.2 R114.1 U16.5(Vp) U17.5(Vp)
VDD12: C28.2 C29.2 C30.2 C31.2 C36.1 C41.2 CB17.1 CB18.1 CB19.1 CB20.1 CB21.1 D10.2 L12.2 R54.2 U8.12(VDD12) U8.21(VDD12) U8.82(VDD12) U8.102(VDD12) U8.146(VDD12) U8.163(VDD12) U8.164(PLL_VDD12) U8.166(VDD12) U8.203(VDD12) U8.204(USBPLL1_VDD) U8.210(USBPLL0_VDD)
VDD18: C25.2 C26.2 C44.1 C47.2 CB5.1 CB6.1 D11.2 L13.2 R58.2 U8.14(MVDD) U8.16(MVDD) U8.18(MVDD) U8.148(MVDD) U8.150(MVDD) U8.152(MVDD)
VDD33: C1.2 C2.2 C18.2 C24.1 C27.2 C32.2 C33.1 C35.2 C51.1 C52.1 C70.1 C71.1 CB1.1 CB2.1 CB3.1 CB7.1 CB8.1 CB9.1 CB10.1 CB11.1 CB12.1 CB13.1 CB14.1 CB15.1 CB16.1 CB24.1 CB27.2 CT1.1 CT2.1 D9.2 D12.1 J1.7(DVDD) J1.39(L/R) J2.1 L7.1 L8.2 L10.2 R1.1 R2.1 R4.2 R5.2 R9.2 R12.2 R14.2 R17.2 R18.2 R19.2 R20.2 R25.1 R27.2 R30.2 R38.1 R42.1 R50.2 R51.1 R60.2 R75.1 R78.2 R79.2 R80.2 R81.2 R82.2 R86.1 R93.1 R97.1 R98.1 R99.1 R102.2 R116.2 U1.12(Vcc) U1.34(NC) U1.37(Vcc) U1.39(NC) U5.8(VCC) U7.6(Vin) U8.10(VDD33) U8.20(VDD33) U8.44(VDD33) U8.80(VDD33) U8.104(VDD33) U8.144(VDD33) U8.154(VDD33) U8.183(VDD33) U8.208(USB1_VDD) U8.214(USB0_VDD) U13.8(VCC) U15.16(VCC) U18.13(IOVDD) U20.3(VCC) U21.16(VCC) U22.2(VCC) U22.14(NC)
12M_XI: C42.1 R56.2 U8.184(MainXi) X2.1(XIN)
12M_XO: C45.1 R56.1 U8.185(MainXo) X2.3(XOUT)
232RXD: U8.24(PF.12/UR2Rx/TM2CAP/Int1) U15.12(R1_OUT)
232TXD: U8.25(PF.11/UR2Tx/TM2TGL/Int0) U15.11(T1_IN)
485_RXD: R63.1 U8.7(PG.12/IIS_DI/SC0_DAT/UR6Rx)
485_TXD: R65.1 U8.8(PG.11/IIS_DO/SC0_CLK/UR6Tx)
485_TXEN: R66.1 U8.6(PG.13/IIS_BCLK/SC0PWR/UR6RTS) U13.2(\\\\RE) U13.3(DE)
CAN_RX0: U8.89(PI.3/SClko/NALE/IIC1SCL/EBI_D3) U20.4(R)
CAN_TX0: U8.90(PI.4/SPClk/NCLE/IIC1SDA/EBI_D4) U20.1(D)
DN1: R73.2 U8.206(USB1_DM)
DP1: R74.2 U8.207(USB1_DP)
ETH_PHY&CAN/50MClki: C62.1 R77.2 U18.10(TxClk/50MClki)
ETH_PHY&CAN/CAN0H: CON7.1 R96.2 U20.7(CANH)
ETH_PHY&CAN/CAN0L: CON7.2 R96.1 U20.6(CANL)
ETH_PHY&CAN/Col: R81.1 U18.4(Col/RMII)
ETH_PHY&CAN/CRS: R82.1 U18.20(CRS/LEDMod)
ETH_PHY&CAN/EthX0: R84.1 R85.1 U18.3(Xo)
ETH_PHY&CAN/EthX1: C63.1 R84.2 U18.2(Xi) X3.1(XIN)
ETH_PHY&CAN/MDI_RN: U18.26(MDiRn) U19.8(RD-)
ETH_PHY&CAN/MDI_RP: U18.27(MDiRp) U19.6(RD+)
ETH_PHY&CAN/MDI_TN: U18.29(MDiTn) U19.3(TD-)
ETH_PHY&CAN/MDI_TP: U18.30(MDiTp) U19.1(TD+)
ETH_PHY&CAN/PhyAD0: CON6.9(LED-) R93.2 U18.11(LED0/PhyAD0)
ETH_PHY&CAN/PhyAD3: R88.1 R95.1 U18.12(LED3/PhyAD3)
ETH_PHY&CAN/RX+: CON6.3(RX+) U19.11(RX+)
ETH_PHY&CAN/RX-: CON6.6(RX-) U19.9(RX-)
ETH_PHY&CAN/TX+: CON6.1(TX+) U19.16(TX+)
ETH_PHY&CAN/TX-: CON6.2(TX-) U19.14(TX-)
FGND: C56.1 C58.1 C61.2 C69.2 C76.2 CM1.4 CON1.6(Shield) CON1.7(Shield) CON1.8(Shield) CON1.9(Shield) CON2.5(Shield) CON2.6(Shield) CON3.2 CON3.3 CON4.5 CON4.10 CON4.11 CON5.5 CON5.10 CON5.11 CON6.11(LED-) L15.1 L17.1 R61.1 R72.1 R95.2 R103.1 R104.1 R105.1 R106.1 R107.1 R108.1 R109.1 R110.1 R111.1 R112.1 R113.1 U16.2(Vn) U17.2(Vn)
FLASH/CD: JP7.9(CD) R16.1 U3.6(CH4)
FLASH/CLK: C3.1 JP7.5(CLK) R10.1 U2.1(CH1)
FLASH/CMD: JP7.3(CMD) R8.1 U2.6(CH4)
FLASH/DAT0: JP7.7(DAT0) R13.1 U3.3(CH2)
FLASH/DAT1: JP7.8(DAT1) R15.1 U3.1(CH1)
FLASH/DAT2: JP7.1(DAT2) R6.1 U2.4(CH3)
FLASH/DAT3: JP7.2(DAT3) R7.1 U2.3(CH2)
FLASH/SPICS_1: R115.1 U5.1(/CS) U22.3(/Rst)
LCD/LCD_RESET: C15.1 J1.44(RESET) R25.2
LCD/LED+: C19.2 D8.2(CATHODE) J1.1(VLED+) J1.2(VLED+) U7.5(OV)
LCD/LED-: J1.3(VLED-) J1.4(VLED-) R31.1 R33.2
LCD_B0: J1.19(B0) RN1.5(13)
LCD_B1: J1.18(B1) RN1.6(14)
LCD_B2: J1.17(B2) RN1.7(15)
LCD_B3: J1.16(B3) RN1.8(16)
LCD_B4: J1.15(B4) RN7.5(13)
LCD_B5: J1.14(B5) RN7.6(14)
LCD_B6: J1.13(B6) RN7.7(15)
LCD_B7: J1.12(B7) RN7.8(16)
LCD_CLK: C11.1 J1.37(DCLK) RN2.5(13)
LCD_G0: J1.27(G0) RN6.5(13)
LCD_G1: J1.26(G1) RN6.6(14)
LCD_G2: J1.25(G2) RN6.7(15)
LCD_G3: J1.24(G3) RN6.8(16)
LCD_G4: J1.23(G4) RN5.5(13)
LCD_G5: J1.22(G5) RN5.6(14)
LCD_G6: J1.21(G6) RN5.7(15)
LCD_G7: J1.20(G7) RN5.8(16)
LCD_R0: J1.35(R0) RN4.5(13)
LCD_R1: J1.34(R1) RN4.6(14)
LCD_R2: J1.33(R2) RN4.7(15)
LCD_R3: J1.32(R3) RN4.8(16)
LCD_R4: J1.31(R4) RN3.5(13)
LCD_R5: J1.30(R5) RN3.6(14)
LCD_R6: J1.29(R6) RN3.7(15)
LCD_R7: J1.28(R7) RN3.8(16)
LHSYNC: J1.11(HS) RN2.7(15)
LVSYNC: J1.10(VS) RN2.8(16)
MAC_REFCLK: R77.1 U8.191(PF.5/RMII0_RefClk) U18.14(RxClk/50M_Clko)
N9H30F61I/BEEPER: R45.1 U8.108(PB.3/UR6Rx/PWM1/TM0CAP)
N9H30F61I/LCLK: RN2.4 U8.29(PG.6/LClk)
N9H30F61I/LD0: RN1.4 SW1.4(B1) U8.54(PA.0/LD0/RMII0_MDC)
N9H30F61I/LD1: RN1.3 SW1.3(B2) U8.53(PA.1/LD1/RMII0_MDio)
N9H30F61I/LD2: RN1.2 U8.52(PA.2/LD2/RMII0_TxD0)
N9H30F61I/LD3: R46.2 RN1.1 U8.51(PA.3/LD3/RMII0_TxD1)
N9H30F61I/LD4: RN7.4 U8.50(PA.4/LD4/KPI_Row0/RMII0_TxEn)
N9H30F61I/LD5: R48.2 RN7.3 U8.49(PA.5/LD5/KPI_Row1RMII0_RefClk)
N9H30F61I/LD6: R40.2 RN7.2 U8.48(PA.6/LD6/KPI_Row2/RMII0_RxD0)
N9H30F61I/LD7: R43.2 RN7.1 U8.47(PA.7/LD7/KPI_Row3/RMII0_RxD1)
N9H30F61I/LD8: R44.2 RN6.4 U8.46(PA.8/LD8/KPI_Col0/RMII0_CRSDV)
N9H30F61I/LD9: R47.2 RN6.3 U8.45(PA.9/LD9/KPI_Col1/RMII0_RxErr)
N9H30F61I/LD10: RN6.2 U8.43(PA.10/LD10/KPI_Col2)
N9H30F61I/LD11: RN6.1 U8.42(PA.11/LD11/KPI_Col3)
N9H30F61I/LD12: RN5.4 U8.41(PA.12/LD12/KPI_Col4/PWM0)
N9H30F61I/LD13: RN5.3 U8.40(PA.13/LD13/KPI_Col5/PWM1)
N9H30F61I/LD14: RN5.2 U8.39(PA.14/LD14/KPI_Col6/PWM2)
N9H30F61I/LD15: RN5.1 U8.38(PA.15/LD15/KPI_Col7/PWM3)
N9H30F61I/LD16: RN4.4 U8.37(PD.8/LD16/EBI_nCS0)
N9H30F61I/LD17: RN4.3 U8.36(PD.9/LD17/EBI_nCS1)
N9H30F61I/LD18: RN4.2 U8.35(PD.10/LD18/EBI_nCS2)
N9H30F61I/LD19: RN4.1 U8.34(PD.11/LD19/UR9Tx/EBI_nCS3)
N9H30F61I/LD20: RN3.4 U8.33(PD.12/LD20/UR9Rx/PWM0/EBI_nCS4)
N9H30F61I/LD21: RN3.3 U8.32(PD.13/LD21/PWM1/EBI_nWE)
N9H30F61I/LD22: RN3.2 U8.31(PD.14/LD22/UR9Tx/PWM2/EBI_nOE)
N9H30F61I/LD23: RN3.1 U8.30(PD.15/LD23/UR9Rx/PWM3/EBI_nWait)
N9H30F61I/LHYNC: RN2.2 U8.28(PG.7/LHsync)
N9H30F61I/LVYNC: RN2.1 U8.27(PG.8/LVsync)
N9H30F61I/nTRST: J2.2 R97.2 U8.142(PJ.4/nTRST)
N9H30F61I/TCK: J2.5 R100.2 U8.139(PJ.0/TCK)
N9H30F61I/TDI: J2.3 R98.2 U8.141(PJ.2/TDI)
N9H30F61I/TDO: J2.6 U8.138(PJ.3/TDO)
N9H30F61I/TMS: J2.4 R99.2 U8.140(PJ.1/TMS)
nRESET: L11.1 U8.143(nRESET)
PH0: R69.1 R72.2 R75.2 U8.198(PH.0/USB0VbusVLD/Int0)
PHY_CRSDV: R83.2 U8.188(PF.8/RMII0_CRSDV) U18.19(RxDV/CRS_DV)
PHY_MDC: U8.196(PF.0/RMII0_MDC) U18.22(MDC)
PHY_MDIO: R79.1 U8.195(PF.1/RMII0_MDio) U18.23(MDIO)
PHY_RST: C77.1 R102.1 U8.197(PH.1/USBOC/Int1) U18.32(nRst)
PHY_RXD0: U8.190(PF.6/RMII0_RxD0) U18.18(RxD0)
PHY_RXD1: U8.189(PF.7/RMII0_RxD1) U18.17(RxD1)
PHY_RXERR: R80.1 U8.187(PF.9/RMII0_RxErr) U18.21(RxEr/Int32)
PHY_TXD0: U8.194(PF.2/RMII0_TxD0) U18.9(TxD0)
PHY_TXD1: U8.193(PF.3/RMII0_TxD1) U18.8(TxD1)
PHY_TXEN: U8.192(PF.4/RMII0_TxEn) U18.5(TxEn)
PhyAVD33: CB25.2 CT3.1 R78.1 U18.31(AVD33)
PWM: R35.1 U8.107(PB.2/UR6Tx/PWM0/TM0TGL)
RegOut: CB26.2 CT4.1 U18.28(RegOut)
RTC_XI: C38.1 U8.69(RTCXi) X1.2
RTC_XO: C39.1 U8.70(RTCXo) X1.1
RTCVD: CB23.1 D12.2 D13.2 U8.66(RTC_VDD)
SDCd: R16.2 R17.1 U8.161(PD.6/SD0CD)
SDCLK: R10.2 U8.156(PD.1/SD0CLK)
SDCmd: R4.1 R8.2 U8.155(PD.0/SD0CMD)
SDD0: R12.1 R13.2 U8.157(PD.2/SD0D0)
SDD1: R14.1 R15.2 U8.158(PD.3/SD0D1)
SDD2: R5.1 R6.2 U8.159(PD.4/SD0D2)
SDD3: R7.2 R9.1 U8.160(PD.5/SD0D3)
SDVD33: JP7.4(VDD) R2.2 U2.5(Vp) U3.5(Vp)
SDVSS: C3.2 JP7.6(VSS) R11.1 U2.2(Vn) U3.2(Vn)
SM_ALE: U1.17(ALE) U8.132(PC.9/NALE/UR10CTS/TM1CAP)
SM_CLE: U1.16(CLE) U8.133(PC.10/NCLE/UR4Tx/TM2TGL)
SM_CS0n: U1.9(~{CE}) U8.131(PC.8/NCS0/UR10RTS/TM1TGL)
SM_D0: U1.29(I/O0) U8.123(PC.0/ND0/eMMC_D0)
SM_D1: U1.30(I/O1) U8.124(PC.1/ND1/eMMC_D1)
SM_D2: U1.31(I/O2) U8.125(PC.2/ND2/eMMC_D2)
SM_D3: U1.32(I/O3) U8.126(PC.3/ND3/eMMC_D3)
SM_D4: U1.41(I/O4) U8.127(PC.4/ND4/eMMC_CMD)
SM_D5: U1.42(I/O5) U8.128(PC.5/ND5/eMMC_CLK)
SM_D6: U1.43(I/O6) U8.129(PC.6/ND6/UR10Tx/TM0TGL)
SM_D7: U1.44(I/O7) U8.130(PC.7/ND7/UR10Tx/TM0CAP)
SM_RBn: R1.2 U1.7(R/~{B}) U8.136(PC.13/NRDY0/UR4CTS/TM3CAP)
SM_REn: U1.8(~{RE}) U8.135(PC.12/NRE/UR4RTS/TM3TGL)
SM_WEn: U1.18(~{WE}) U8.134(PC.11/NWE/UR4Rx/TM2CAP)
SM_WPn: R3.1 U1.19(~{WP}) U8.137(PC.14/NWP/PWM0)
SPICLK: U5.6(CLK) U8.112(PB.7/SPI0Clk) U22.12(NC) U22.16(CLK)
SPICS: R19.1 R115.2 U8.111(PB.6/SPI0CS0) U22.7(CS)
SPIDi/D1: U5.2(Do/D1) U8.114(PB.9/SPI0Di(D1)) U22.4(NC) U22.8(Do/D1)
SPIDo/D0: U5.5(Di/D0) U8.113(PB.8/SPI0Do(D0)) U22.11(NC) U22.15(Di/D0)
SPIHOLD/D3: R20.1 U5.7(Hld/D3) U8.116(PB.11/UR10Rx/SPI0D3/CAN0Tx) U22.1(Hld/D3) U22.13(NC)
SPIWp/D2: R18.1 U5.3(Wp/D2) U8.115(PB.10/UR10Tx/SPI0D2/CAN0Rx) U22.5(NC) U22.9(Wp/D2)
UART0_RX: U8.181(PE.1/UR0Rx) U21.12(R1_OUT)
UART0_TX: U8.182(PE.0/UR0Tx) U21.11(T1_IN)
UART/232U0RXD: CON5.3 U21.13(R1_IN)
UART/232U0TXD: CON5.2 U21.14(T1_OUT)
UART/232URXD: CON4.3 U15.13(R1_IN)
UART/232UTXD: CON4.2 U15.14(T1_OUT)
UART/485_A: JP5.1 R67.2 RS485_1.1
UART/485_B: JP5.2 R62.2 RS485_1.2
USB0_DM: R70.2 U8.212(USB0_DM)
USB0_DP: R71.2 U8.213(USB0_DP)
USB/D1+: CON2.3(D+) R74.1 U17.6(CH4)
USB/D1-: CON2.2(D-) R73.1 U17.4(CH3)
USB/UDO0: CON1.2(D-) R70.1 U16.4(CH3)
USB/UDO1: CON1.3(D+) R71.1 U16.6(CH4)
VCOM: C9.2 D4.2(CATHODE) J1.6(VCOM) J1.46(VCOM) R22.2
VGH: C13.2 D6.2(CATHODE) J1.41(VGH) R24.1 R26.1
VGL: C8.2 D3.1(ANODE) J1.42(VGL) R21.1 R23.1
X+: L6.2 U8.60(ADC7)
X-: L4.2 U8.56(ADC6)
Y+: L3.2 U8.61(ADC5)
Y-: L5.2 U8.57(ADC4)
ETH_PHY&CAN/N02976: C65.1 R85.2 R87.2
ETH_PHY&CAN/N03018: R87.1 X3.3(XOUT)
ETH_PHY&CAN/N03204: R76.2 U18.25(Iset)
ETH_PHY&CAN/N34630: R91.2 U19.10(CT)
ETH_PHY&CAN/N34634: C69.1 R89.1 R90.1 R91.1 R92.1
ETH_PHY&CAN/N34664: R92.2 U19.15(CT)
ETH_PHY&CAN/N34668: CON6.7(NC) CON6.8(NC) R89.2
ETH_PHY&CAN/N34684: CON6.4(NC) CON6.5(NC) R90.2
ETH_PHY&CAN/N34752: C76.1 CON6.13(Shield) CON6.14(Shield)
ETH_PHY&CAN/N34786: CON6.10(LED+) R86.2
ETH_PHY&CAN/N34796: CON6.12(LED+) R88.2
ETH_PHY&CAN/N35142: C64.1 C66.1 U19.2(CT)
ETH_PHY&CAN/N35180: C67.1 C68.1 U19.7(CT)
ETH_PHY&CAN/N16750192: R94.2 U20.8(Rs)
FLASH/N16176709: JP7.10(GND) JP7.11(GND) JP7.12(GND) L1.2
LCD/N16168470: Q1.1(GATE) U6.5(EXT)
LCD/N16168512: C4.2 C6.2 C10.2 D7.1(ANODE) L2.1 Q1.3(DRAIN)
LCD/N16168671: C16.1 R28.1 R29.2 U6.1(FB)
LCD/N16168934: R34.1 U6.3(CE)
LCD/N16169469: C10.1 D5.3
LCD/N16169473: C6.1 D2.3
LCD/N16169477: C4.1 D1.3
LCD/N16169727: C12.2 D5.2 R24.2
LCD/N16170221: C7.2 D2.1 R21.2
LCD/N16170876: C5.2 D1.1 D2.2
LCD/N16213146: D8.1(ANODE) L7.2 U7.1(SW)
LCD/N16213372: CB4.1 R30.1 U7.4(EN)
LCD/N16213420: R31.2 R32.1 U7.3(FB)
LCD/N16213608: C21.2 R32.2 R35.2
LCD/N16216669: J1.47(DITHB) R27.1
LCD/N16224745: D17.2 L4.1 TOUCH1.1
LCD/N16224749: D18.2 L3.1 TOUCH1.2
LCD/N16224753: D19.2 L6.1 TOUCH1.3
LCD/N16224757: D20.2 L5.1 TOUCH1.4
N9H30F61I/N16171270: R39.2 SW1.1(A1)
N9H30F61I/N16171458: R41.2 SW1.2(A2)
N9H30F61I/N16172341: R38.2 U8.216(USB0_ID)
N9H30F61I/N16174427: C22.1 U8.65(Vref)
N9H30F61I/N16175784: R37.1 U8.209(USB1_Rext)
N9H30F61I/N16176080: R36.1 U8.215(USB0_Rext)
N9H30F61I/N16777490: Q2.2 R42.2
N9H30F61I/N16777516: Q2.1 R45.2
N9H30F61I/N16777518: BZ1.1(+) Q2.3
POWER/N02313: L10.1 U9.3(SW)
POWER/N02385: C32.1 R50.1 R52.2 U9.5(FB)
POWER/N02707: C40.1 R53.1 U11.1(EN)
POWER/N02771: L12.1 U11.3(SW)
POWER/N02855: C36.2 R54.1 R55.1 U11.5(FB)
POWER/N03241: C46.1 R57.1 U12.1(EN)
POWER/N03303: L13.1 U12.3(SW)
POWER/N03375: C44.2 R58.1 R59.1 U12.5(FB)
POWER/N16759936: BT1.2 D13.1
POWER/N16762062: LED1.1(ANODE) R60.1
POWER/N16785567: R49.1 U10.1(GND)
POWER/N16785682: R51.2 U10.4(VCC)
POWER/N16786009: JP8.1 R116.1 U10.3(/MR)
POWER/N16786032: L11.2 U10.2(/RESET)
UART/N04254: D14.2 R61.2 R62.1 R64.2 U13.7(B)
UART/N04374: R63.2 U13.1(RO)
UART/N04444: D14.1 R64.1 R67.1 R68.1 U13.6(A)
UART/N04458: R65.2 U13.4(DI)
UART/N16775151: C53.1 U15.1(C1+)
UART/N16775163: C51.2 U15.2(V+)
UART/N16775243: C53.2 U15.3(C1-)
UART/N16775269: C54.1 U15.4(C2+)
UART/N16775289: C54.2 U15.5(C2-)
UART/N16775325: C55.1 U15.6(V-)
UART/N16784871: C72.1 U21.1(C1+)
UART/N16784877: C70.2 U21.2(V+)
UART/N16784925: C72.2 U21.3(C1-)
UART/N16784938: C73.1 U21.4(C2+)
UART/N16784948: C73.2 U21.5(C2-)
UART/N16784966: C74.1 U21.6(V-)
USB/N00286: C75.1 CON1.1(VBUS) L14.2
USB/N16172403: C75.2 CON1.5(GND) L15.2
USB/N16173903: C57.1 CON2.1(VBUS) L16.2
USB/N16174021: C57.2 CON2.4(GND) L17.2

Not connected (* = marked no-connect by the designer): CON1 4(ID)*; CON4 1* 4* 6* 7* 8* 9*; CON5 1* 4* 6* 7* 8* 9*; J1 45(NC) 49(NC) 50(NC); JP7 13(GND); T1 1; T2 1; T3 1*; T4 1*; U1 1(NC)* 2(NC)* 3(NC)* 4(NC)* 5(NC)* 6(NC)* 10(NC)* 11(NC)* 14(NC)* 15(NC)* 20(NC)* 21(NC)* 22(NC)* 23(NC)* 24(NC)* 26(NC)* 27(NC)* 28(NC)* 33(NC)* 35(NC)* 38(NC) 40(NC)* 45(NC)* 46(NC)* 47(NC)*; U3 4(CH3); U8 1(PG.3/IIC1SDA) 2(PG.2/IIC1SCL) 3(PG.1/IIC0SDA) 4(PG.0/IIC0SCL) 5(PG.14/IIS_LRCK/SC0CD/UR6CTS) 9(PG.10/IIS_MClk/SC0_RST) 22(PF.14/UR2CTS/TM3CAP/Int3) 23(PF.13/UR2RTS/TM3TGL/Int2) 26(PG.9/LDEN) 55(ADC0) 62(ADC1) 63(ADC3) 64(ADC2) 67(SysPWREn) 68(SysnWkUp)* 71(PH.4/KPI_Row0/UR1Tx/EBI_Add0/Int4) 72(PH.5/KPI_Row1/UR1Rx/EBI_Add1/Int5) 73(PH.6/KPI_Row2/SD1Cmd/UR1RTS/EBI_Add2/Int6) 74(PH.7/KPI_Row3/SD1Clk/UR1CTS/EBI_Add3/Int7) 75(PH.8/KPI_Col0/SD1D0/UR4Tx/EBI_Add4) 76(PH.9/KPI_Col1/SD1D1/UR4Rx/EBI_Add5) 77(PH.10/KPI_Col2/SD1D2/UR4RTS/EBI_Add6) 78(PH.11/KPI_Col3/SD1D3/UR4CTS/EBI_Add7) 79(PH.12/KPI_Cl4/SD1CD/UR8Tx/SPI0CS1/EBI_Add8) 83(PH.13/KPI_Col5/SD1PWR/UR8Rx/SPI1CS1/EBI_Add9) 84(PH.14/KPI_Col6/UR8RTS/CAN1Rx/EBI_nBE0) 85(PH.15/KPI_Col7/UR8CTS/CAN1Tx/EBI_nBE1) 86(PI.0/EBI_D0) 87(PI.1/NCS0/UR7Tx/EBI_D1/Int6) 88(PI.2/NWP/UR7Rx/EBI_D2/Int7) 91(PI.5/SHsync/NWE/eMMC_Cmd/EBI_D5/SD1CMD) 92(PI.6/SVsync/NRE/eMMC_Clk/SC1_Rst/EBI_D6/SD1CLK) 93(PI.7/SField/NRDY0/eMMC_D3/SC1_Clk/EBI_D7/SD1D0) 94(PI.8/SD0/ND0/eMMC_D0/SC1_DAT/EBI_D8/SD1D1) 95(PI.9/SD1/ND1/eMMC_D1/SC1_PWR/EBI_D9/SD1D2) 96(PI.10/SD2/ND2/eMMC_D2/SC1_CD/EBI_D10/SD1D3) 97(PI.11/SD3/ND3/SC0_Rst/EBI_D11) 98(PI.12/SD4/ND4/UR8Tx/SC0_Clk/EBI_D12/SD1CD) 99(PI.13/SD5/ND5/UR8Rx/SC0_DAT/EBI_D13/SD1PWR) 100(PI.14/SD6/ND6/UR8RTS/SC0_PWR/EBI_D14) 101(PI.15/SD7/ND7/UR8CTS/SC0_CD/EBI_D15) 105(PB.0/NCS1/IIC1SCL/UR5Tx/SPI0CS1/TM1TGL) 106(PB.1/NRDY1/IIC1SDA/UR5Rx/SPI1CS1/TM1CAP) 109(PB.4/UR6RTS) 110(PB.5/UR6CTS) 117(PB.12/UR10Tx/SPI1CS0) 118(PB.13/UR10Rx/SPI1Clk) 119(PB.14/UR10RTS/SPI1Do(D0)) 120(PB.15/UR10CTS/SPI1Di(D1)) 121(PG.4/NCS1/UR7Tx/SPI1D2) 122(PG.5/NRDY1/UR7Rx/SPI1D3) 162(PD.7/SD0PWR) 167(PH.3/IIC1SDA/UR9Rx/CAN0Tx/PWM3/Int3) 168(PH.2/IIC1SCL/UR9Tx/CAN0Rx/PWM2/Int2) 169(PE.13/UR8CTS/UR3Rx) 170(PE.12/UR8RTS/UR3Tx) 171(PE.11/RMII1_RxErr/UR8Rx) 172(PE.10/RMII1_CRSDV/UR8Tx) 173(PE.9/RMII1_RxD1/SD1PWR/UR1CD) 174(PE.8/RMII1_RxD0/SD1CD/UR1Ri) 175(PE.7/RMII1_RefClk/SD1D3/UR1DSR) 176(PE.6/RMII1_TxEn/SD1D2/UR1DTR) 177(PE.5/RMII1_TxD1/SD1D1/UR1CTS) 178(PE.4/RMII1_TxD0/SD1D0/UR1RTS) 179(PE.3/RMII1_MDIO/SD1CLK/UR1Rx) 180(PE.2/RMII1_MDC/SD1CMD/UR1Tx) 199(PF.10/USBPWREn/WDT_nRst) 200(PE.15/USB1PWREn) 201(PE.14/USB0PWREn); U15 7(T2_OUT)* 8(R2_IN)* 9(R2_OUT)* 10(T2_IN)*; U16 1(CH1)* 3(CH2)*; U17 1(CH1)* 3(CH2)*; U18 1(TxEr/FxSD)* 6(TxD3)* 7(TxD2)* 15(RxD3)* 16(RxD2)* 24(TestOn)*; U19 4(NC)* 5(NC)* 12(NC)* 13(NC)*; U20 5(Vref)*; U21 7(T2_OUT)* 8(R2_IN)* 9(R2_OUT)* 10(T2_IN)*

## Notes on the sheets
sheet 4
- NAND FLASH
- TF CARD
- SPI Falsh
sheet 5
- EthernetT Port
sheet 6
- RS485
- RS232
- RS232
sheet 7
- USB0 Device
- USB Host
sheet 8
- RESET
- 32768Hz Crystal
- 12MHz Crystal
